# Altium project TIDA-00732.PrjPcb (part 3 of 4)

## Sheet TIDA-00732_Pwr.SchDoc: LDO's Isolated & Non Isolated
size 431 x 279 mm; Date: Not shown in title block; ApprovedBy: Not shown in title block; CheckedBy: Not shown in title block; Author: Not shown in title block; CompanyName: Not shown in title block; DrawnBy: Anbu Mani; Engineer: Not shown in title block; Organization: Not shown in title block; Address1: Not shown in title block; Address2: Not shown in title block; Address3: Not shown in title block; Address4: Not shown in title block; DocumentNumber: 1; Revision: Use project parameter SCH_Rev; SheetNumber: 7; SheetTotal: 10; PageSetup: Record=PageOptions¦CenterHorizontal=True¦CenterVertical=True¦PrintScale=1.00¦XCorrection=1.00¦YCorrection=1.00¦PrintKind=0¦BorderSize=5000000¦LeftOffset=0¦BottomOffset=0¦Orientation=2¦PaperLength=1000¦PaperWidth=1000¦Scale=100¦PaperSource=15¦PrintQuality=600¦MediaType=1¦DitherType=10¦PaperKind=Letter¦PrintScaleMode=1
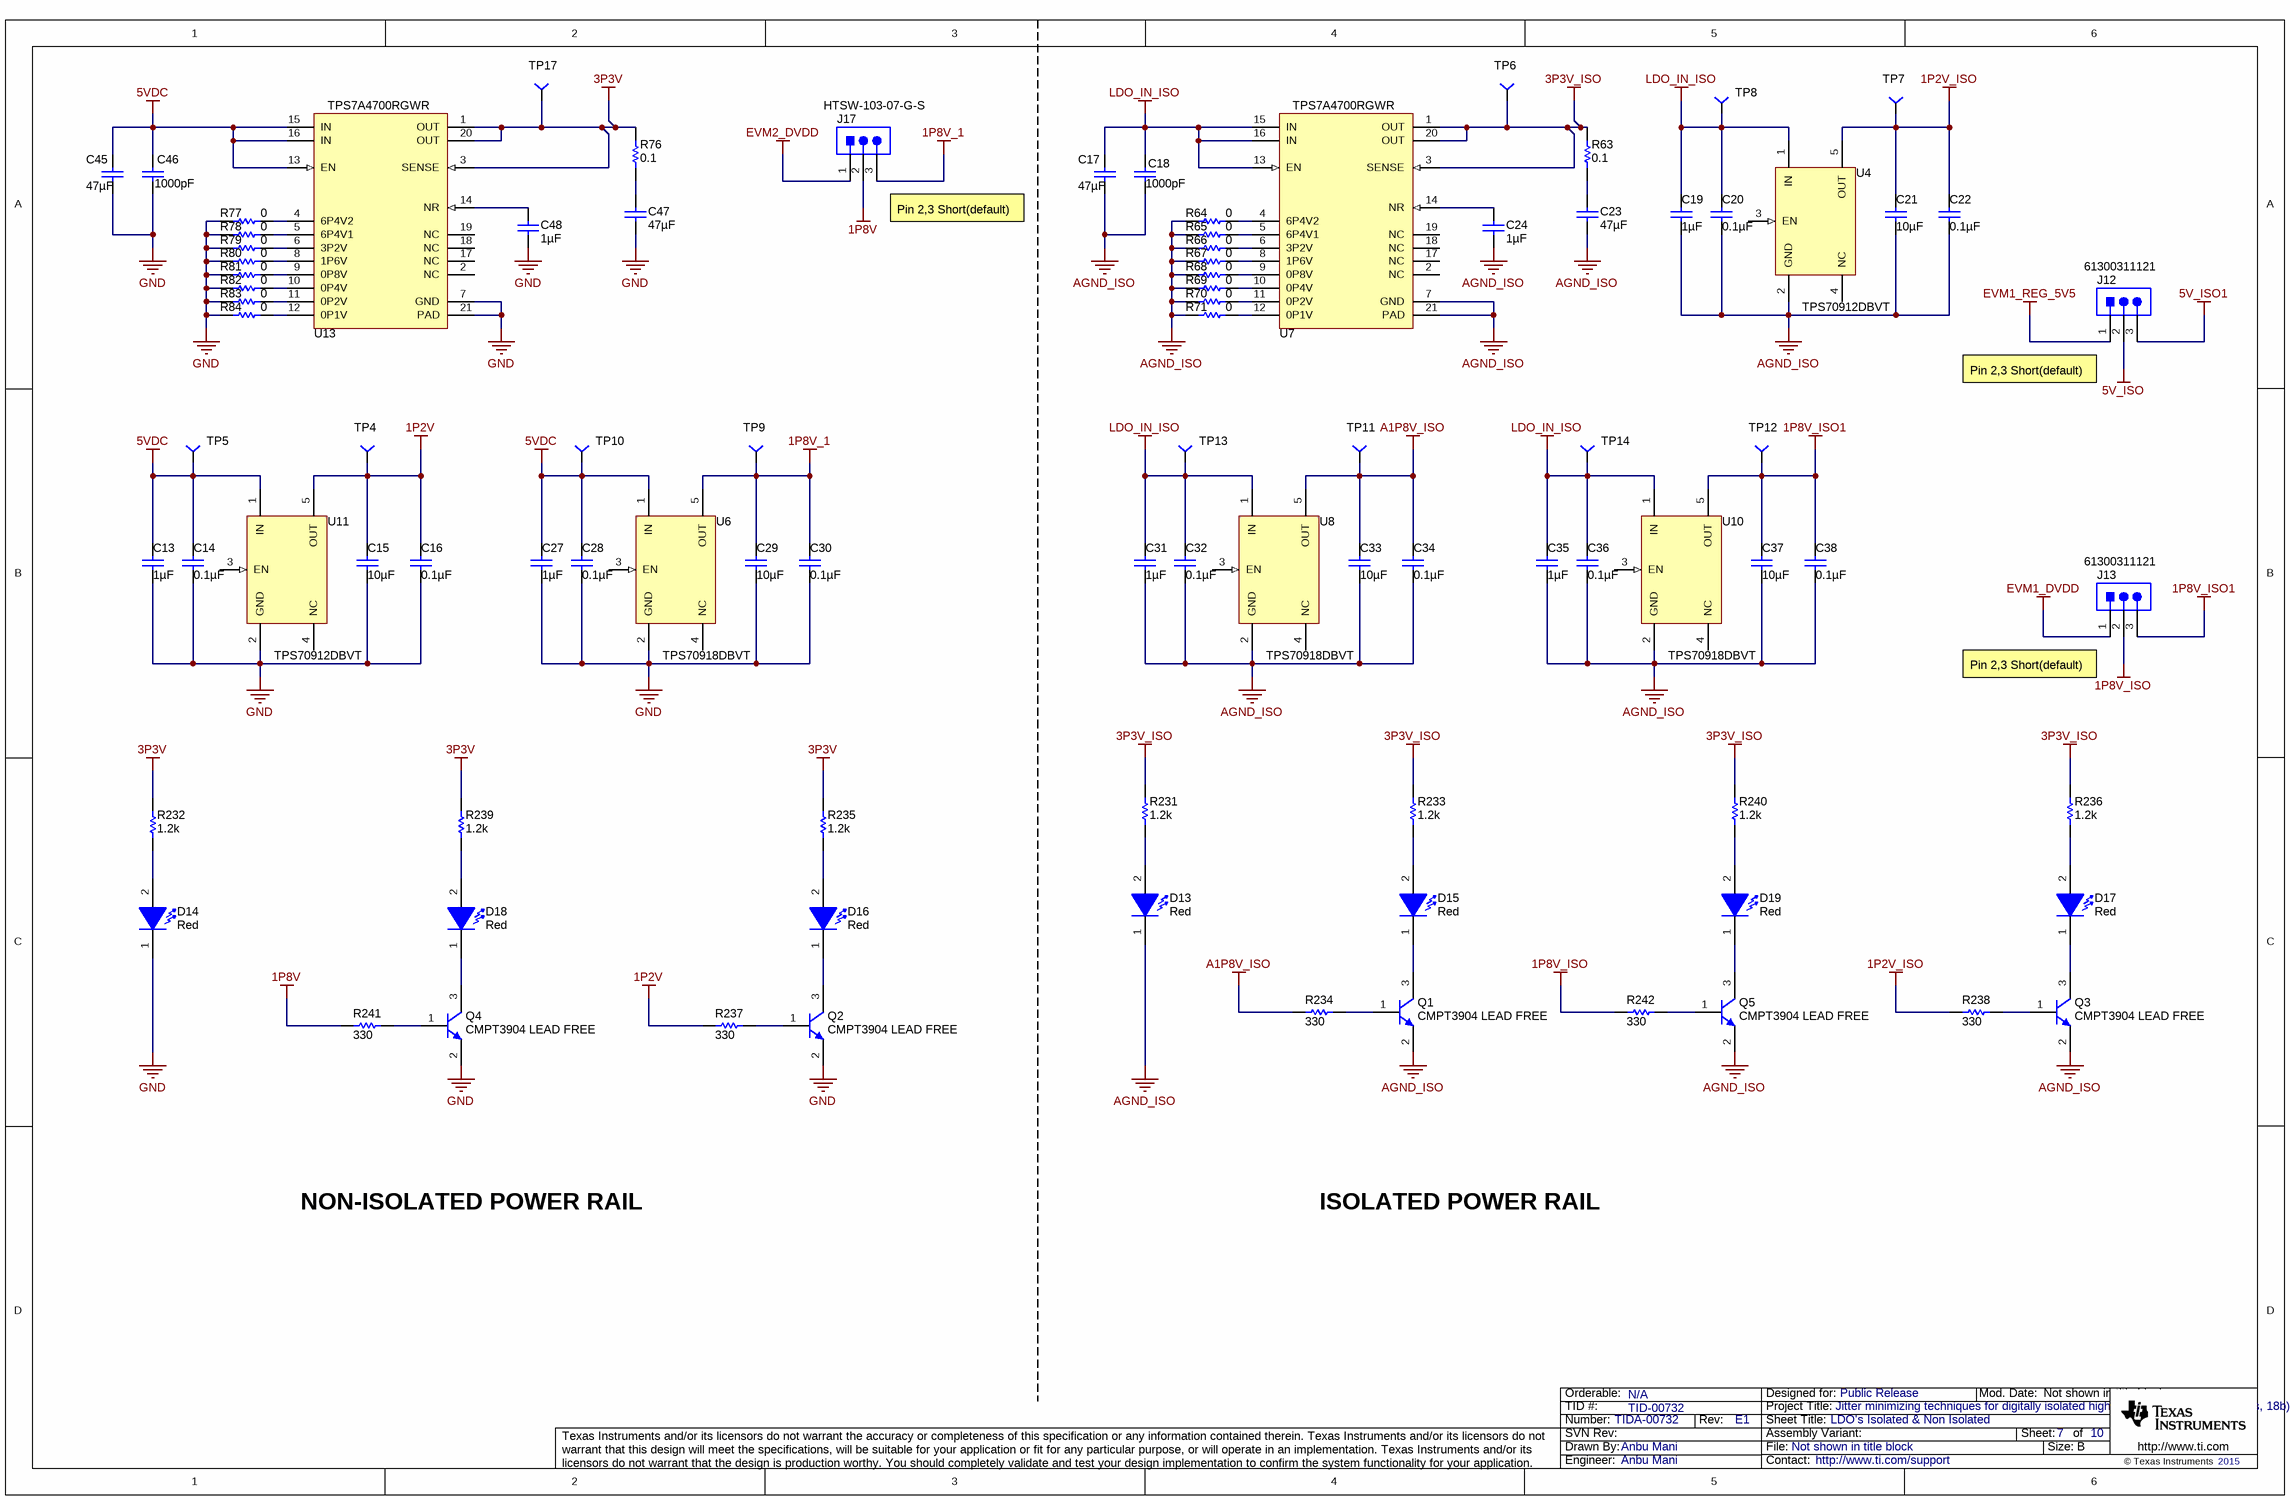
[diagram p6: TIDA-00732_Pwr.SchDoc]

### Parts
C13  ValueDisplayed: 1µF  [0805]  (hidden comment: 08055C105KAT2A)
C14  ValueDisplayed: 0.1µF  [0603]  (hidden comment: C0603C104K5RACTU)
C15  ValueDisplayed: 10µF  [0805]  (hidden comment: 0805YD106MAT2A)
C16  ValueDisplayed: 0.1µF  [0603]  (hidden comment: C0603C104K5RACTU)
C17  ValueDisplayed: 47µF  [1206_190]  (hidden comment: C3216X5R1E476M160AC)
C18  ValueDisplayed: 1000pF  [0603]  (hidden comment: GRM1885C1H102FA01J)
C19  ValueDisplayed: 1µF  [0805]  (hidden comment: 08055C105KAT2A)
C20  ValueDisplayed: 0.1µF  [0603]  (hidden comment: C0603C104K5RACTU)
C21  ValueDisplayed: 10µF  [0805]  (hidden comment: 0805YD106MAT2A)
C22  ValueDisplayed: 0.1µF  [0603]  (hidden comment: C0603C104K5RACTU)
C23  ValueDisplayed: 47µF  [1206_190]  (hidden comment: C3216X5R1E476M160AC)
C24  ValueDisplayed: 1µF  [0603]  (hidden comment: GRM188R71E105KA12D)
C27  ValueDisplayed: 1µF  [0805]  (hidden comment: 08055C105KAT2A)
C28  ValueDisplayed: 0.1µF  [0603]  (hidden comment: C0603C104K5RACTU)
C29  ValueDisplayed: 10µF  [0805]  (hidden comment: 0805YD106MAT2A)
C30  ValueDisplayed: 0.1µF  [0603]  (hidden comment: C0603C104K5RACTU)
C31  ValueDisplayed: 1µF  [0805]  (hidden comment: 08055C105KAT2A)
C32  ValueDisplayed: 0.1µF  [0603]  (hidden comment: C0603C104K5RACTU)
C33  ValueDisplayed: 10µF  [0805]  (hidden comment: 0805YD106MAT2A)
C34  ValueDisplayed: 0.1µF  [0603]  (hidden comment: C0603C104K5RACTU)
C35  ValueDisplayed: 1µF  [0805]  (hidden comment: 08055C105KAT2A)
C36  ValueDisplayed: 0.1µF  [0603]  (hidden comment: C0603C104K5RACTU)
C37  ValueDisplayed: 10µF  [0805]  (hidden comment: 0805YD106MAT2A)
C38  ValueDisplayed: 0.1µF  [0603]  (hidden comment: C0603C104K5RACTU)
C45  ValueDisplayed: 47µF  [1206_190]  (hidden comment: C3216X5R1E476M160AC)
C46  ValueDisplayed: 1000pF  [0603]  (hidden comment: GRM1885C1H102FA01J)
C47  ValueDisplayed: 47µF  [1206_190]  (hidden comment: C3216X5R1E476M160AC)
C48  ValueDisplayed: 1µF  [0603]  (hidden comment: GRM188R71E105KA12D)
D13  value Red  [WL-SMCW_RED]  (hidden comment: 150060RS75000)
D14  value Red  [WL-SMCW_RED]  (hidden comment: 150060RS75000)
D15  value Red  [WL-SMCW_RED]  (hidden comment: 150060RS75000)
D16  value Red  [WL-SMCW_RED]  (hidden comment: 150060RS75000)
D17  value Red  [WL-SMCW_RED]  (hidden comment: 150060RS75000)
D18  value Red  [WL-SMCW_RED]  (hidden comment: 150060RS75000)
D19  value Red  [WL-SMCW_RED]  (hidden comment: 150060RS75000)
J12  61300311121  [WURTH_61300311121]
J13  61300311121  [WURTH_61300311121]
J17  HTSW-103-07-G-S  [Samtec_HTSW-103-07-G-S]
Q1  CMPT3904 LEAD FREE  [SOT-23]
Q2  CMPT3904 LEAD FREE  [SOT-23]
Q3  CMPT3904 LEAD FREE  [SOT-23]
Q4  CMPT3904 LEAD FREE  [SOT-23]
Q5  CMPT3904 LEAD FREE  [SOT-23]
R63  ValueDisplayed: 0.1  [0603]  (hidden comment: ERJ-3RSFR10V)
R64  ValueDisplayed: 0  [0402]  (hidden comment: ERJ-2GE0R00X)
R65  ValueDisplayed: 0  [0402]  (hidden comment: ERJ-2GE0R00X)
R66  ValueDisplayed: 0  [0402]  (hidden comment: ERJ-2GE0R00X)
R67  ValueDisplayed: 0  [0402]  (hidden comment: ERJ-2GE0R00X)
R68  ValueDisplayed: 0  [0402]  (hidden comment: ERJ-2GE0R00X)
R69  ValueDisplayed: 0  [0402]  (hidden comment: ERJ-2GE0R00X)
R70  ValueDisplayed: 0  [0402]  (hidden comment: ERJ-2GE0R00X)
R71  ValueDisplayed: 0  [0402]  (hidden comment: ERJ-2GE0R00X)
R76  ValueDisplayed: 0.1  [0603]  (hidden comment: ERJ-3RSFR10V)
R77  ValueDisplayed: 0  [0402]  (hidden comment: ERJ-2GE0R00X)
R78  ValueDisplayed: 0  [0402]  (hidden comment: ERJ-2GE0R00X)
R79  ValueDisplayed: 0  [0402]  (hidden comment: ERJ-2GE0R00X)
R80  ValueDisplayed: 0  [0402]  (hidden comment: ERJ-2GE0R00X)
R81  ValueDisplayed: 0  [0402]  (hidden comment: ERJ-2GE0R00X)
R82  ValueDisplayed: 0  [0402]  (hidden comment: ERJ-2GE0R00X)
R83  ValueDisplayed: 0  [0402]  (hidden comment: ERJ-2GE0R00X)
R84  ValueDisplayed: 0  [0402]  (hidden comment: ERJ-2GE0R00X)
R231  ValueDisplayed: 1.2k  [0603]  (hidden comment: CRCW06031K20JNEA)
R232  ValueDisplayed: 1.2k  [0603]  (hidden comment: CRCW06031K20JNEA)
R233  ValueDisplayed: 1.2k  [0603]  (hidden comment: CRCW06031K20JNEA)
R234  ValueDisplayed: 330  [0603]  (hidden comment: RC0603JR-07330RL)
R235  ValueDisplayed: 1.2k  [0603]  (hidden comment: CRCW06031K20JNEA)
R236  ValueDisplayed: 1.2k  [0603]  (hidden comment: CRCW06031K20JNEA)
R237  ValueDisplayed: 330  [0603]  (hidden comment: RC0603JR-07330RL)
R238  ValueDisplayed: 330  [0603]  (hidden comment: RC0603JR-07330RL)
R239  ValueDisplayed: 1.2k  [0603]  (hidden comment: CRCW06031K20JNEA)
R240  ValueDisplayed: 1.2k  [0603]  (hidden comment: CRCW06031K20JNEA)
R241  ValueDisplayed: 330  [0603]  (hidden comment: RC0603JR-07330RL)
R242  ValueDisplayed: 330  [0603]  (hidden comment: RC0603JR-07330RL)
TP4  TP1_PD40_D0.5_S50  [TP-040_RND]  (value not drawn)
TP5  TP1_PD40_D0.5_S50  [TP-040_RND]  (value not drawn)
TP6  TP1_PD40_D0.5_S50  [TP-040_RND]  (value not drawn)
TP7  TP1_PD40_D0.5_S50  [TP-040_RND]  (value not drawn)
TP8  TP1_PD40_D0.5_S50  [TP-040_RND]  (value not drawn)
TP9  TP1_PD40_D0.5_S50  [TP-040_RND]  (value not drawn)
TP10  TP1_PD40_D0.5_S50  [TP-040_RND]  (value not drawn)
TP11  TP1_PD40_D0.5_S50  [TP-040_RND]  (value not drawn)
TP12  TP1_PD40_D0.5_S50  [TP-040_RND]  (value not drawn)
TP13  TP1_PD40_D0.5_S50  [TP-040_RND]  (value not drawn)
TP14  TP1_PD40_D0.5_S50  [TP-040_RND]  (value not drawn)
TP17  TP1_PD40_D0.5_S50  [TP-040_RND]  (value not drawn)
U4  TPS70912DBVT  [DBV0005A_N]
U6  TPS70918DBVT  [DBV0005A_N]
U7  TPS7A4700RGWR  [RGW0020A]
U8  TPS70918DBVT  [DBV0005A_N]
U10  TPS70918DBVT  [DBV0005A_N]
U11  TPS70912DBVT  [DBV0005A_N]
U13  TPS7A4700RGWR  [RGW0020A]

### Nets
1P2V: C15.1 C16.1 R237.2 TP4.1 U11.5(OUT)
1P2V_ISO: C21.1 C22.1 R238.2 TP7.1 U4.5(OUT)
1P8V: J17.2 R241.2
1P8V_1: C29.1 C30.1 J17.3 TP9.1 U6.5(OUT)
1P8V_ISO: J13.2 R242.2
1P8V_ISO1: C37.1 C38.1 J13.3 TP12.1 U10.5(OUT)
3P3V: R76.2 R232.2 R235.2 R239.2 TP17.1 U13.1(OUT) U13.3(SENSE) U13.20(OUT)
3P3V_ISO: R63.2 R231.2 R233.2 R236.2 R240.2 TP6.1 U7.1(OUT) U7.3(SENSE) U7.20(OUT)
5V_ISO: J12.2
5V_ISO1: J12.3
5VDC: C13.1 C14.1 C27.1 C28.1 C45.1 C46.1 TP5.1 TP10.1 U6.1(IN) U11.1(IN) U13.13(EN) U13.15(IN) U13.16(IN)
A1P8V_ISO: C33.1 C34.1 R234.2 TP11.1 U8.5(OUT)
AGND_ISO: C17.2 C18.2 C19.2 C20.2 C21.2 C22.2 C23.2 C24.1 C31.2 C32.2 C33.2 C34.2 C35.2 C36.2 C37.2 C38.2 D13.1(K) Q1.2(E) Q3.2(E) Q5.2(E) R64.1 R65.1 R66.1 R67.1 R68.1 R69.1 R70.1 R71.1 U4.2(GND) U7.7(GND) U7.21(PAD) U8.2(GND) U10.2(GND)
EVM1_DVDD: J13.1
EVM1_REG_5V5: J12.1
EVM2_DVDD: J17.1
GND: C13.2 C14.2 C15.2 C16.2 C27.2 C28.2 C29.2 C30.2 C45.2 C46.2 C47.2 C48.1 D14.1(K) Q2.2(E) Q4.2(E) R77.1 R78.1 R79.1 R80.1 R81.1 R82.1 R83.1 R84.1 U6.2(GND) U11.2(GND) U13.7(GND) U13.21(PAD)
LDO_IN_ISO: C17.1 C18.1 C19.1 C20.1 C31.1 C32.1 C35.1 C36.1 TP8.1 TP13.1 TP14.1 U4.1(IN) U7.13(EN) U7.15(IN) U7.16(IN) U8.1(IN) U10.1(IN)
NetC23_1: C23.1 R63.1
NetC24_2: C24.2 U7.14(NR)
NetC47_1: C47.1 R76.1
NetC48_2: C48.2 U13.14(NR)
NetD13_2: D13.2(A) R231.1
NetD14_2: D14.2(A) R232.1
NetD15_1: D15.1(K) Q1.3(C)
NetD15_2: D15.2(A) R233.1
NetD16_1: D16.1(K) Q2.3(C)
NetD16_2: D16.2(A) R235.1
NetD17_1: D17.1(K) Q3.3(C)
NetD17_2: D17.2(A) R236.1
NetD18_1: D18.1(K) Q4.3(C)
NetD18_2: D18.2(A) R239.1
NetD19_1: D19.1(K) Q5.3(C)
NetD19_2: D19.2(A) R240.1
NetQ1_1: Q1.1(B) R234.1
NetQ2_1: Q2.1(B) R237.1
NetQ3_1: Q3.1(B) R238.1
NetQ4_1: Q4.1(B) R241.1
NetQ5_1: Q5.1(B) R242.1
NetR64_2: R64.2 U7.4(6P4V2)
NetR65_2: R65.2 U7.5(6P4V1)
NetR66_2: R66.2 U7.6(3P2V)
NetR67_2: R67.2 U7.8(1P6V)
NetR68_2: R68.2 U7.9(0P8V)
NetR69_2: R69.2 U7.10(0P4V)
NetR70_2: R70.2 U7.11(0P2V)
NetR71_2: R71.2 U7.12(0P1V)
NetR77_2: R77.2 U13.4(6P4V2)
NetR78_2: R78.2 U13.5(6P4V1)
NetR79_2: R79.2 U13.6(3P2V)
NetR80_2: R80.2 U13.8(1P6V)
NetR81_2: R81.2 U13.9(0P8V)
NetR82_2: R82.2 U13.10(0P4V)
NetR83_2: R83.2 U13.11(0P2V)
NetR84_2: R84.2 U13.12(0P1V)

Not connected (* = marked no-connect by the designer): U4 3(EN) 4(NC); U6 3(EN) 4(NC); U7 2(NC) 17(NC) 18(NC) 19(NC); U8 3(EN) 4(NC); U10 3(EN) 4(NC); U11 3(EN) 4(NC); U13 2(NC) 17(NC) 18(NC) 19(NC)

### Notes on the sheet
- (near J17) Pin 2,3 Short(default)
- (near J12) Pin 2,3 Short(default)
- (near J13) Pin 2,3 Short(default)
- NON-ISOLATED POWER RAIL
- ISOLATED POWER RAIL

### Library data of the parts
C13 C19 C27 C31 C35 = 08055C105KAT2A: CAP, CERM, 1uF, 50V, +/-10%, X7R, 0805; Manufacturer: AVX; Polarized: N; CompType: Capacitor; U/M: EA; Cap_F: 0.000001; Tolerance_%: 10; Value1: Unknown; VDC_V: 50; TaMin_C: -55; TaMax_C: 125
C14 C16 C20 C22 C28 C30 C32 C34 C36 C38 = C0603C104K5RACTU: CAP, CERM, 0.1uF, 50V, +/-10%, X7R, 0603; Manufacturer: Kemet; Polarized: N; CompType: Capacitor; U/M: EA; Cap_F: 0.0000001; Tolerance_%: 10; Value1: Unknown; VDC_V: 50; TaMin_C: -55; TaMax_C: 125
C15 C21 C29 C33 C37 = 0805YD106MAT2A: CAP, CERM, 10uF, 16V, +/-20%, X5R, 0805; Manufacturer: AVX; Polarized: N; CompType: Capacitor; U/M: EA; Cap_F: 0.00001; Tolerance_%: 20; Value1: Unknown; VDC_V: 16; TaMin_C: -55; TaMax_C: 85
C17 C23 C45 C47 = C3216X5R1E476M160AC: CAP, CERM, 47 µF, 25 V, +/- 20%, X5R, 1206_190; Manufacturer: TDK; Polarized: N; CompType: Capacitor; Value: 47uF; U/M: EA; Cap_F: 0.000047; Tolerance_%: 20; Value1: Unknown; VDC_V: 25; Value2: 25V; TaMin_C: -55; TaMax_C: 85; Cap_Case: 1206; AEC Category: Q200
C18 C46 = GRM1885C1H102FA01J: CAP, CERM, 1000 pF, 50 V, +/- 1%, C0G/NP0, 0603; Manufacturer: MuRata; Polarized: N; CompType: Capacitor; Value: 1000pF; U/M: EA; Cap_F: 0.000000001; Tolerance_%: 1; Value1: Unknown; VDC_V: 50; Value2: 50V; TaMin_C: -55; TaMax_C: 125; AEC Category: Q200
C24 C48 = GRM188R71E105KA12D: CAP, CERM, 1 µF, 25 V, +/- 10%, X7R, 0603; Manufacturer: MuRata; Polarized: N; CompType: Capacitor; Value: 1uF; U/M: EA; Cap_F: 0.000001; Tolerance_%: 10; Value1: Unknown; VDC_V: 25; Value2: 25V; TaMin_C: -55; TaMax_C: 125; AEC Category: Q200
D13-D19 = 150060RS75000: LED, Red, SMD; Manufacturer: Wurth Elektronik; Type: AlInGaP; Vf_V: 2; Value2: 2V; Io_A: 0.03; Vr_V: 5; Tjmax_C: 85; Power_TotalModule: 0.072; Value1: 0.072W; Angle: 140; U/M: EA
J12 J13 = 61300311121: Header, 2.54 mm, 3x1, Gold, TH; Manufacturer: Wurth Elektronik eiSos; SymbolCreator: a0799628; U/M: EA
J17 = HTSW-103-07-G-S: Header, 100mil, 3x1, Gold, TH; Manufacturer: Samtec; SymbolCreator: a0799628; U/M: EA
Q1-Q5 = CMPT3904 LEAD FREE, Central Semiconductor: Transistor, NPN, 40 V, 0.2 A, SOT-23; CompType: BJT; PNP: 0; NPN: 1; Vceo_V: 40; Vcesat1_V: 0.2; Value: 40 V; Value1: 0.2 A; TaMin_C: -65; TaMax_C: 150; U/M: EA; AEC Category: Q101
R63 R76 = ERJ-3RSFR10V: RES, 0.1, 1%, 0.1 W, 0603; Manufacturer: Panasonic; CompType: Resistor; Value: 0.1; Value_Code: R100; Tolerance_%: 1; Value2: 0.1W; TempCo: 300 ppm/C; EIA_Code: E96; U/M: EA; AEC Category: Q200
R64-R71 R77-R84 = ERJ-2GE0R00X: RES, 0, 5%, 0.063 W, 0402; Manufacturer: Panasonic; CompType: Resistor; Value: 0; Value_Code: 0000; Tolerance_%: 5; Power_W: 0.063; Value2: 0.063W; VDC_V: 50; TempCo: 600 ppm/C; EIA_Code: E24; U/M: EA; AEC Category: Q200
R231-R233 R235 R236 R239 R240 = CRCW06031K20JNEA: RES, 1.2 k, 5%, 0.1 W, 0603; Manufacturer: Vishay-Dale; CompType: Resistor; Value: 1.2k; Res_ohm: 1200; Value_Code: 1k20; Tolerance_%: 5; Power_W: 0.1; Value2: 0.1W; VDC_V: 75; TempCo: 200 ppm/C; EIA_Code: E24; U/M: EA; AEC Category: Q200
R234 R237 R238 R241 R242 = RC0603JR-07330RL: RES, 330, 5%, 0.1 W, 0603; Manufacturer: Yageo America; CompType: Resistor; Value: 330; Value_Code: 330R; Tolerance_%: 5; Power_W: 0.1; Value2: 0.1W; VDC_V: 50; TempCo: 100 ppm/C; EIA_Code: E24; U/M: EA; AEC Category: Q200
TP4-TP14 TP17 = TP-040_RND: Test Point 40mil pad 20mil drill; Manufacturer: STD; Value: STD
U4 U11 = TPS70933DBVT: IC REG LDO 1.2V 0.15A SOT23-5; Alternate Manufacturer: None; Manufacturer: Texas Instruments; SymbolCreator: a0411947; U/M: EA
U6 U8 U10 = TPS70933DBVT: IC REG LDO 1.8V 0.15A SOT23-5; Alternate Manufacturer: None; Manufacturer: Texas Instruments; SymbolCreator: a0411947; U/M: EA
U7 U13 = TPS7A4700RGWR: 36-V, 1-A, 4.17-μVRMS, RF LDO Voltage Regulator, RGW0020A; Alternate PartNumber: TPS7A4700RGWT; Manufacturer: Texas Instruments; SymbolCreator: a0412235; CompType: IC; U/M: EA

## Sheet TIDA-00732_Pwr_Sense.SchDoc: Power Sense - PH1 & PH2  Interface
size 431 x 279 mm; Date: Not shown in title block; ApprovedBy: Not shown in title block; CheckedBy: Not shown in title block; Author: Not shown in title block; CompanyName: Not shown in title block; DrawnBy: Anbu Mani; Engineer: Not shown in title block; Organization: Not shown in title block; Address1: Not shown in title block; Address2: Not shown in title block; Address3: Not shown in title block; Address4: Not shown in title block; DocumentNumber: 1; Revision: Use project parameter SCH_Rev; SheetNumber: 8; SheetTotal: 10; PageSetup: Record=PageOptions¦CenterHorizontal=True¦CenterVertical=True¦PrintScale=1.00¦XCorrection=1.00¦YCorrection=1.00¦PrintKind=0¦BorderSize=5000000¦LeftOffset=0¦BottomOffset=0¦Orientation=2¦PaperLength=1000¦PaperWidth=1000¦Scale=100¦PaperSource=15¦PrintQuality=600¦MediaType=1¦DitherType=10¦PaperKind=Letter¦PrintScaleMode=1
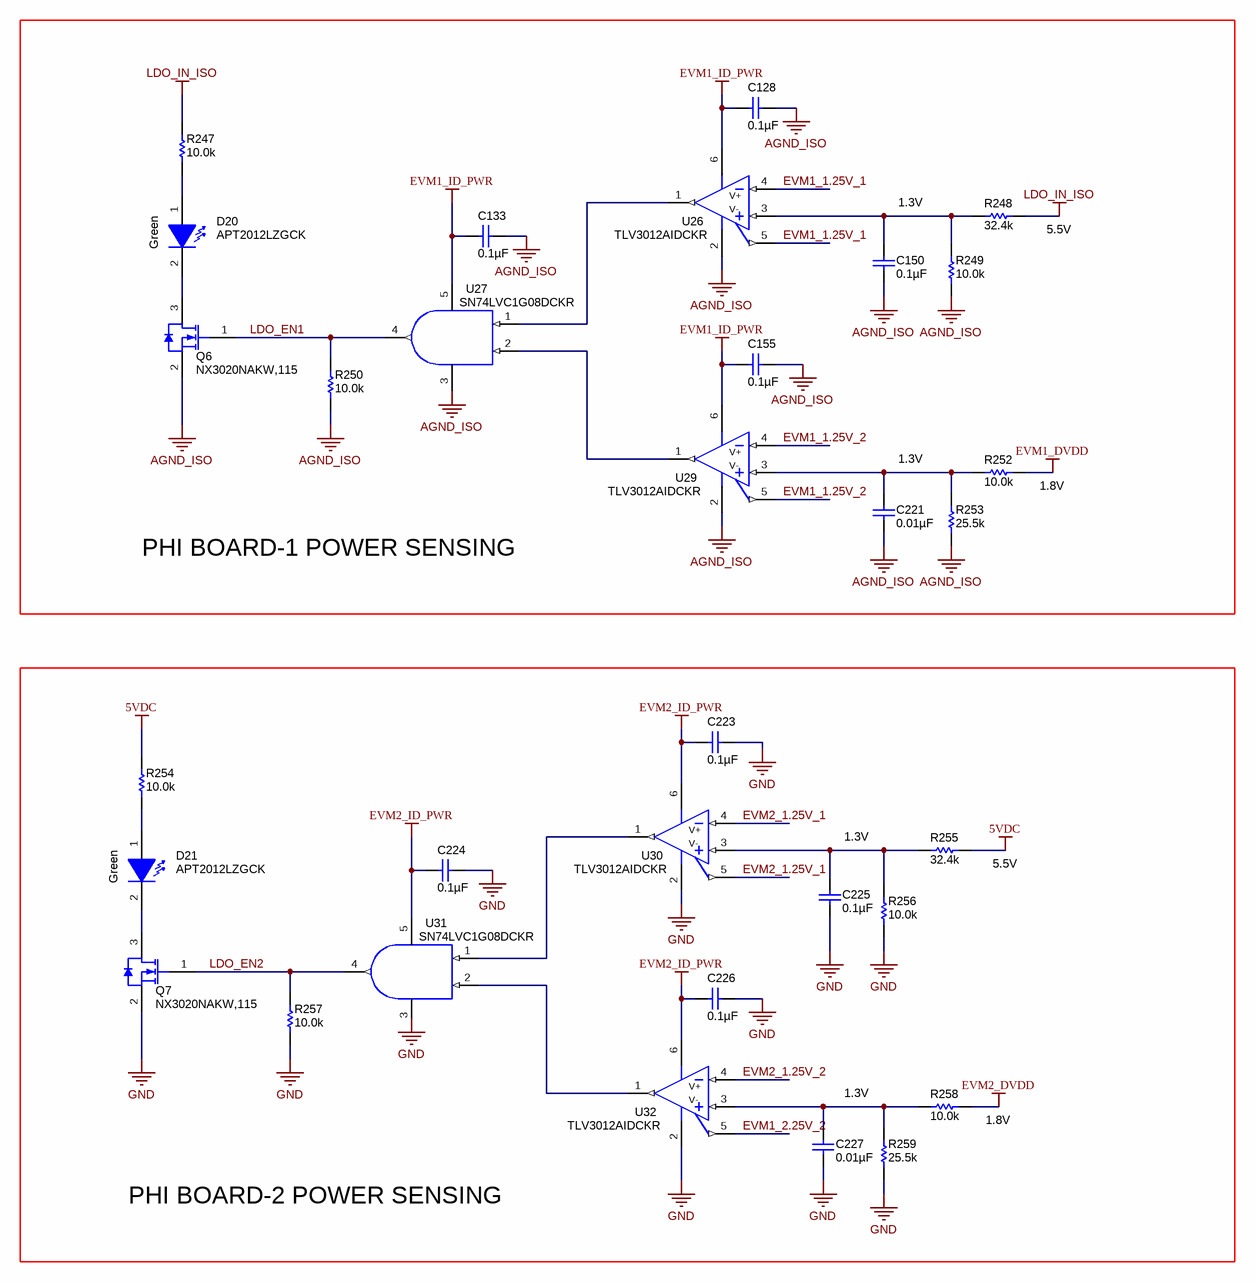
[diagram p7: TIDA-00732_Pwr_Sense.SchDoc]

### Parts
C128  ValueDisplayed: 0.1µF  [0402]  (hidden comment: GRM155R71C104KA88D)
C133  ValueDisplayed: 0.1µF  [0402]  (hidden comment: GRM155R71C104KA88D)
C150  ValueDisplayed: 0.1µF  [0402]  (hidden comment: GRM155R71C104KA88D)
C155  ValueDisplayed: 0.1µF  [0402]  (hidden comment: GRM155R71C104KA88D)
C221  ValueDisplayed: 0.01µF  [0402]  (hidden comment: GRM155R71H103KA88D)
C223  ValueDisplayed: 0.1µF  [0402]  (hidden comment: GRM155R71C104KA88D)
C224  ValueDisplayed: 0.1µF  [0402]  (hidden comment: GRM155R71C104KA88D)
C225  ValueDisplayed: 0.1µF  [0402]  (hidden comment: GRM155R71C104KA88D)
C226  ValueDisplayed: 0.1µF  [0402]  (hidden comment: GRM155R71C104KA88D)
C227  ValueDisplayed: 0.01µF  [0402]  (hidden comment: GRM155R71H103KA88D)
D20  value Green  [APT2012_Green]  (hidden comment: APT2012LZGCK)
D21  value Green  [APT2012_Green]  (hidden comment: APT2012LZGCK)
Q6  NX3020NAKW,115  [SOT-323]
Q7  NX3020NAKW,115  [SOT-323]
R247  ValueDisplayed: 10.0k  [0402]  (hidden comment: ERJ-2RKF1002X)
R248  ValueDisplayed: 32.4k  [0603_HV]  (hidden comment: RG1608P-3242-B-T5)
R249  ValueDisplayed: 10.0k  [0603_HV]  (hidden comment: RG1608P-103-B-T5)
R250  ValueDisplayed: 10.0k  [0402]  (hidden comment: ERJ-2RKF1002X)
R252  ValueDisplayed: 10.0k  [0603_HV]  (hidden comment: RG1608P-103-B-T5)
R253  ValueDisplayed: 25.5k  [0603_HV]  (hidden comment: RG1608P-2552-B-T5)
R254  ValueDisplayed: 10.0k  [0402]  (hidden comment: ERJ-2RKF1002X)
R255  ValueDisplayed: 32.4k  [0603_HV]  (hidden comment: RG1608P-3242-B-T5)
R256  ValueDisplayed: 10.0k  [0603_HV]  (hidden comment: RG1608P-103-B-T5)
R257  ValueDisplayed: 10.0k  [0402]  (hidden comment: ERJ-2RKF1002X)
R258  ValueDisplayed: 10.0k  [0603_HV]  (hidden comment: RG1608P-103-B-T5)
R259  ValueDisplayed: 25.5k  [0603_HV]  (hidden comment: RG1608P-2552-B-T5)
U26  TLV3012AIDCKR  [DCK0006A_L]
U27  SN74LVC1G08DCKR  [DCK0005A_L]
U29  TLV3012AIDCKR  [DCK0006A_L]
U30  TLV3012AIDCKR  [DCK0006A_L]
U31  SN74LVC1G08DCKR  [DCK0005A_L]
U32  TLV3012AIDCKR  [DCK0006A_L]

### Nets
5VDC: R254.2 R255.2
AGND_ISO: C128.1 C133.1 C150.2 C155.1 C221.2 Q6.2(S) R249.1 R250.1 R253.1 U26.2(V-) U27.3(V-) U29.2(V-)
EVM1_DVDD: R252.2
EVM1_ID_PWR: C128.2 C133.2 C155.2 U26.6(V+) U27.5(V+) U29.6(V+)
EVM2_DVDD: R258.2
EVM2_ID_PWR: C223.2 C224.2 C226.2 U30.6(V+) U31.5(V+) U32.6(V+)
GND: C223.1 C224.1 C225.2 C226.1 C227.2 Q7.2(S) R256.1 R257.1 R259.1 U30.2(V-) U32.2(V-)
LDO_IN_ISO: R247.2 R248.2
EVM1_1.25V_1: U26.4(IN-) U26.5(REF)
EVM1_1.25V_2: U29.4(IN-) U29.5(REF)
EVM1_2.25V_2: U32.5(REF)
EVM2_1.25V_1: U30.4(IN-) U30.5(REF)
EVM2_1.25V_2: U32.4(IN-)
LDO_EN1: Q6.1(G) R250.2 U27.4(Y)
LDO_EN2: Q7.1(G) R257.2 U31.4(Y)
NetC150_1: C150.1 R248.1 R249.2 U26.3(IN+)
NetC221_1: C221.1 R252.1 R253.2 U29.3(IN+)
NetC225_1: C225.1 R255.1 R256.2 U30.3(IN+)
NetC227_1: C227.1 R258.1 R259.2 U32.3(IN+)
NetD20_1: D20.1(A) R247.1
NetD20_2: D20.2(K) Q6.3(D)
NetD21_1: D21.1(A) R254.1
NetD21_2: D21.2(K) Q7.3(D)
NetU26_1: U26.1(OUT) U27.1(A)
NetU27_2: U27.2(B) U29.1(OUT)
NetU30_1: U30.1(OUT) U31.1(A)
NetU31_2: U31.2(B) U32.1(OUT)

Not connected (* = marked no-connect by the designer): U31 3(V-)

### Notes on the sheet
- 1.3V
- (near R248) 5.5V
- (near R252) 1.8V
- PHI BOARD-1 POWER SENSING
- (near R255) 5.5V
- (near R258) 1.8V
- PHI BOARD-2 POWER SENSING
- Labels drawn without touching a wire or pin: GND

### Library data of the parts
C128 C133 C150 C155 C223-C226 = GRM155R71C104KA88D: CAP, CERM, 0.1 µF, 16 V, +/- 10%, X7R, 0402; Manufacturer: MuRata; Polarized: N; CompType: Capacitor; Value: 0.1uF; U/M: EA; Cap_F: 0.0000001; Tolerance_%: 10; Value1: Unknown; VDC_V: 16; Value2: 16V; TaMin_C: -55; TaMax_C: 125; AEC Category: Q200
C221 C227 = GRM155R71H103KA88D: CAP, CERM, 0.01 µF, 50 V, +/- 10%, X7R, 0402; Manufacturer: MuRata; Polarized: N; CompType: Capacitor; Value: 0.01uF; U/M: EA; Cap_F: 0.00000001; Tolerance_%: 10; Value1: Unknown; VDC_V: 50; Value2: 50V; TaMin_C: -55; TaMax_C: 125; AEC Category: Q200
D20 D21 = APT2012LZGCK: LED, Green, SMD; Manufacturer: Kingbright; Type: InGaN; Vf_V: 2.65; Value2: 2.65V; Io_A: 0.002; Vr_V: 5; Ir_A: 5e-005; Tjmax_C: 85; Power_TotalModule: 0.075; Value1: 0.075W; Angle: 120; U/M: EA
Q6 Q7 = NX3020NAKW,115: MOSFET, N-CH, 30 V, 0.18 A, SOT-323; Manufacturer: NXP Semiconductor; Alternate Manufacturer: None; U/M: EA; ChType: N; Value: 30V; VdsMax_V: 30; Value1: 5.2 ohm; Rdson45_ohm: 5.2; Value2: 0.34 nC; QgTyp_nC: 0.34; Vgs_V: 20; IdsMax_A: 0.18; AEC Category: Q101
R247 R250 R254 R257 = ERJ-2RKF1002X: RES, 10.0 k, 1%, 0.1 W, 0402; Manufacturer: Panasonic; CompType: Resistor; Value: 10.0k; Res_ohm: 10000; Value_Code: 10k0; Tolerance_%: 1; Power_W: 0.1; Value2: 0.1W; VDC_V: 50; TempCo: 100 ppm/C; EIA_Code: E96; U/M: EA; AEC Category: Q200
R248 R255 = RG1608P-3242-B-T5: RES, 32.4 k, 0.1%, 0.1 W, 0603; Manufacturer: Susumu Co Ltd; CompType: Resistor; Value: 32.4k; Res_ohm: 32400; Value_Code: 32k4; Tolerance_%: 0.1; Value2: 0.1W; VDC_V: 75; TempCo: 25 ppm/C; EIA_Code: E192; U/M: EA; AEC Category: Q200
R249 R252 R256 R258 = RG1608P-103-B-T5: RES, 10.0 k, 0.1%, 0.1 W, 0603; Manufacturer: Susumu Co Ltd; CompType: Resistor; Value: 10.0k; Res_ohm: 10000; Value_Code: 10k0; Tolerance_%: 0.1; Value2: 0.1W; VDC_V: 75; TempCo: 25 ppm/C; EIA_Code: E192; U/M: EA; AEC Category: Q200
R253 R259 = RG1608P-2552-B-T5: RES, 25.5 k, 0.1%, 0.1 W, 0603; Manufacturer: Susumu Co Ltd; CompType: Resistor; Value: 25.5k; Res_ohm: 25500; Value_Code: 25k5; Tolerance_%: 0.1; Value2: 0.1W; VDC_V: 75; TempCo: 25 ppm/C; EIA_Code: E192; U/M: EA; AEC Category: Q200
U26 U29 U30 U32 = TLV3012AIDCKR: Nanopower, 1.8V, Comparator with Voltage Reference, DCK0006A; Alternate PartNumber: TLV3012AIDCKT; Manufacturer: Texas Instruments; SymbolCreator: a0411595/a0412235; CompType: IC; U/M: EA
U27 U31 = SN74LVC1G08DCKR: Single 2-Input Positive-AND Gate, DCK0005A; Alternate PartNumber: SN74LVC1G08DCKT; Manufacturer: Texas Instruments; CompType: IC; U/M: EA

## Sheet TIDA-00732_ADC_Ref_Select.SchDoc: ADC Reference Selection
size 431 x 279 mm; Date: Not shown in title block; ApprovedBy: Not shown in title block; CheckedBy: Not shown in title block; Author: Not shown in title block; CompanyName: Not shown in title block; DrawnBy: Anbu Mani; Engineer: Not shown in title block; Organization: Not shown in title block; Address1: Not shown in title block; Address2: Not shown in title block; Address3: Not shown in title block; Address4: Not shown in title block; DocumentNumber: 1; Revision: Use project parameter SCH_Rev; SheetNumber: 9; SheetTotal: 10; PageSetup: Record=PageOptions¦CenterHorizontal=True¦CenterVertical=True¦PrintScale=1.00¦XCorrection=1.00¦YCorrection=1.00¦PrintKind=0¦BorderSize=5000000¦LeftOffset=0¦BottomOffset=0¦Orientation=2¦PaperLength=1000¦PaperWidth=1000¦Scale=100¦PaperSource=15¦PrintQuality=600¦MediaType=1¦DitherType=10¦PaperKind=Letter¦PrintScaleMode=1
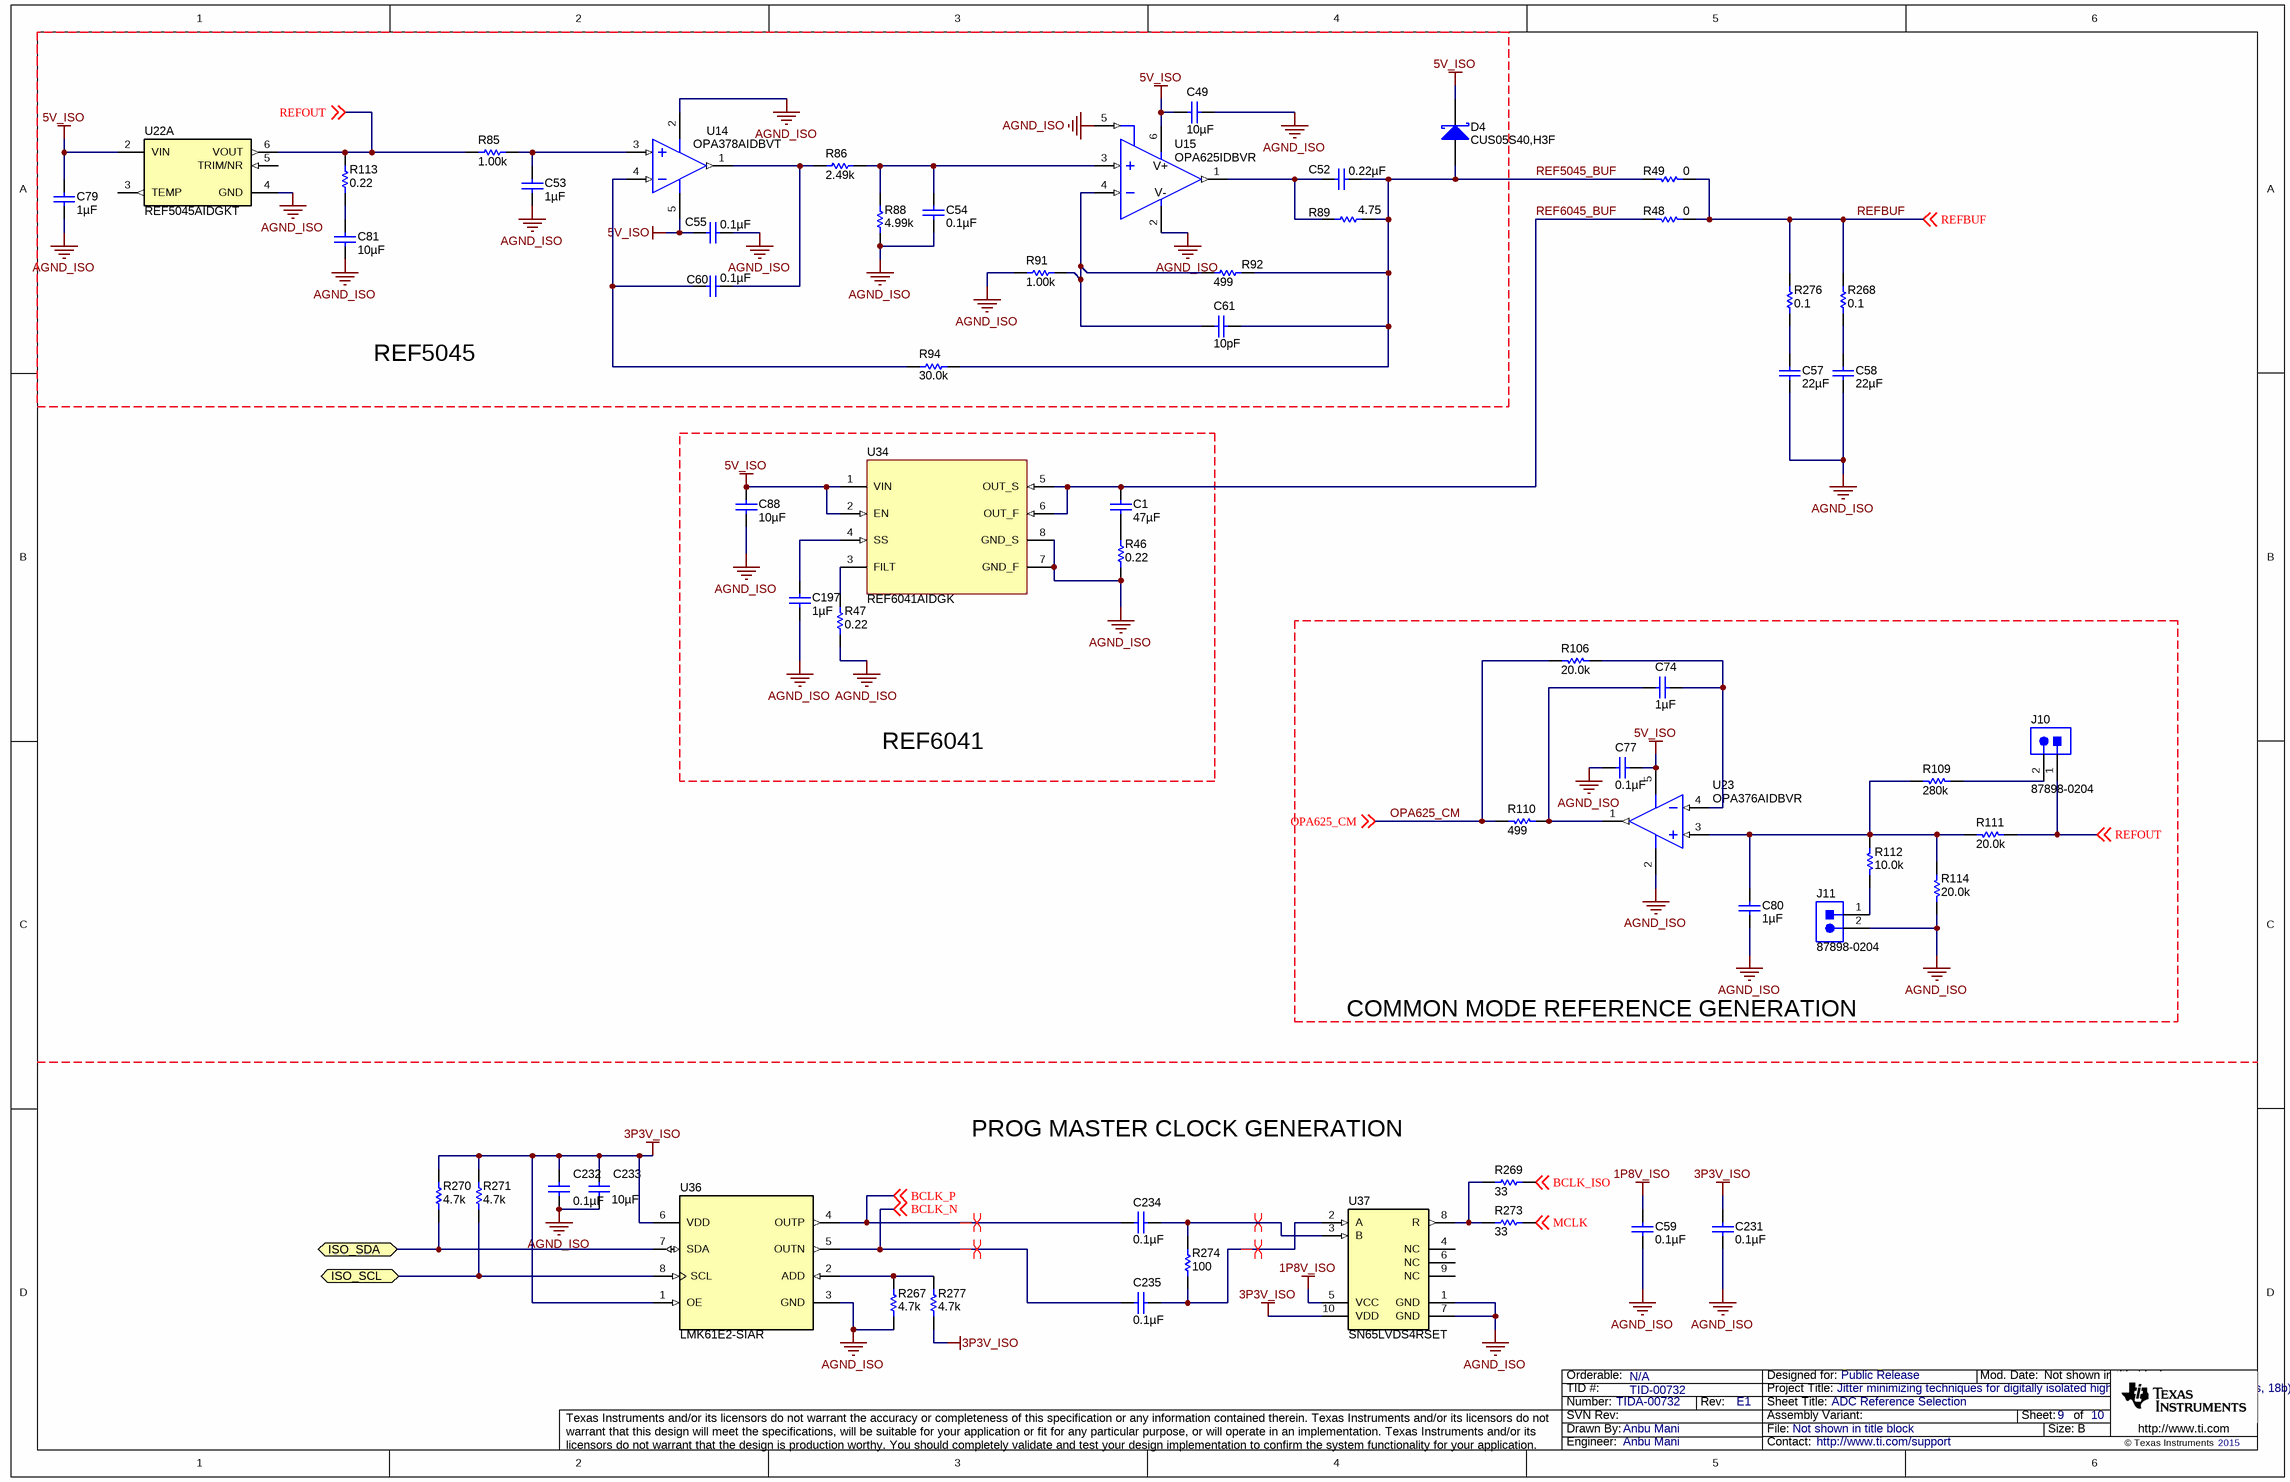
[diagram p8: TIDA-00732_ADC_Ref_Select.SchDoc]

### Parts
C1  ValueDisplayed: 47µF  [1210]  (hidden comment: GRM32ER71A476KE15L)
C49  ValueDisplayed: 10µF  [0603_120]  (hidden comment: ZRB18AD71A106KE01L)
C52  ValueDisplayed: 0.22µF  [0805_HV]  (hidden comment: 0805YC224JAT2A)
C53  ValueDisplayed: 1µF  [0603]  (hidden comment: GRM188R71E105KA12D)
C54  ValueDisplayed: 0.1µF  [0603]  (hidden comment: C0603C104J3RACTU)
C55  ValueDisplayed: 0.1µF  [0603]  (hidden comment: C0603C104J3RACTU)
C57  ValueDisplayed: 22µF  [0603]  (hidden comment: GRM188R60J226MEA0J)
C58  ValueDisplayed: 22µF  [0603]  (hidden comment: GRM188R60J226MEA0J)
C59  ValueDisplayed: 0.1µF  [0402]  (hidden comment: GRM155R71C104KA88D)
C60  ValueDisplayed: 0.1µF  [0603]  (hidden comment: C0603C104J3RACTU)
C61  ValueDisplayed: 10pF  [0603]  (hidden comment: C0603C100F5GAC7867)
C74  ValueDisplayed: 1µF  [0603]  (hidden comment: GRM188R71E105KA12D)
C77  ValueDisplayed: 0.1µF  [0603]  (hidden comment: C0603C104J3RACTU)
C79  ValueDisplayed: 1µF  [0603]  (hidden comment: GRM188R71E105KA12D)
C80  ValueDisplayed: 1µF  [0603]  (hidden comment: GRM188R71E105KA12D)
C81  ValueDisplayed: 10µF  [0805_HV]  (hidden comment: GRM21BR71A106KE51L)
C88  ValueDisplayed: 10µF  [0805]  (hidden comment: GRM21BR71A106KE51L)
C197  ValueDisplayed: 1µF  [0603]  (hidden comment: GRM188R71A105KA61D)
C231  ValueDisplayed: 0.1µF  [0402]  (hidden comment: GRM155R71C104KA88D)
C232  ValueDisplayed: 0.1µF  [0603]  (hidden comment: C0603C104J3RACTU)
C233  ValueDisplayed: 10µF  [0603_120]  (hidden comment: ZRB18AD71A106KE01L)
C234  ValueDisplayed: 0.1µF  [0402]  (hidden comment: GRM155R61E104KA87D)
C235  ValueDisplayed: 0.1µF  [0402]  (hidden comment: GRM155R61E104KA87D)
D4  CUS05S40,H3F  [sod-323]
J10  87898-0204  [Molex_87898-0204]
J11  87898-0204  [Molex_87898-0204]
R46  value 0.22  [0603]  (hidden comment: ERJ-3RQFR22V)
R47  value 0.22  [0603]  (hidden comment: ERJ-3RQFR22V)
R48  ValueDisplayed: 0  [0603]  (hidden comment: ERJ-3GEY0R00V)
R49  ValueDisplayed: 0  [0603]  (hidden comment: ERJ-3GEY0R00V)
R85  ValueDisplayed: 1.00k  [0603]  (hidden comment: RG1608P-102-B-T5)
R86  ValueDisplayed: 2.49k  [0603]  (hidden comment: RG1608P-2491-B-T5)
R88  ValueDisplayed: 4.99k  [0603]  (hidden comment: RG1608P-4991-B-T5)
R89  ValueDisplayed: 4.75  [0603]  (hidden comment: CRCW06034R75FKEA)
R91  ValueDisplayed: 1.00k  [0603]  (hidden comment: RG1608P-102-B-T5)
R92  ValueDisplayed: 499  [0603]  (hidden comment: RG1608P-4990-B-T5)
R94  ValueDisplayed: 30.0k  [0603]  (hidden comment: RG1608P-303-B-T5)
R106  ValueDisplayed: 20.0k  [0603]  (hidden comment: RG1608P-203-B-T5)
R109  ValueDisplayed: 280k  [0805_HV]  (hidden comment: RG2012P-2803-B-T5)
R110  ValueDisplayed: 499  [0603]  (hidden comment: RG1608P-4990-B-T5)
R111  ValueDisplayed: 20.0k  [0603]  (hidden comment: RG1608P-203-B-T5)
R112  ValueDisplayed: 10.0k  [0603]  (hidden comment: RG1608P-103-B-T5)
R113  ValueDisplayed: 0.22  [0603]  (hidden comment: ERJ-3RQFR22V)
R114  ValueDisplayed: 20.0k  [0603]  (hidden comment: RG1608P-203-B-T5)
R267  ValueDisplayed: 4.7k  [0402]  (hidden comment: CRCW04024K70JNED)
R268  ValueDisplayed: 0.1  [0402]  (hidden comment: ERJ-2BSFR10X)
R269  ValueDisplayed: 33  [0402]  (hidden comment: CRCW040233R0JNED)
R270  ValueDisplayed: 4.7k  [0402]  (hidden comment: CRCW04024K70JNED)
R271  ValueDisplayed: 4.7k  [0402]  (hidden comment: CRCW04024K70JNED)
R273  ValueDisplayed: 33  [0402]  (hidden comment: CRCW040233R0JNED)
R274  ValueDisplayed: 100  [0402]  (hidden comment: CRCW0402100RJNED)
R276  ValueDisplayed: 0.1  [0402]  (hidden comment: ERJ-2BSFR10X)
R277  ValueDisplayed: 4.7k  [0402]  (hidden comment: CRCW04024K70JNED)
U14  OPA378AIDBVT  [DBV0005A_N]
U15  OPA625IDBVR  [DBV0006A_N]
U22  REF5045AIDGKT  [DGK0008A_N]  (part A of 2)
U23  OPA376AIDBVR  [DBV0005A_N]
U34  REF6041AIDGK  [DGK0008A_N]
U36  LMK61E2-SIAR  [SIA0008B]
U37  SN65LVDS4RSET  [RSE0010A]

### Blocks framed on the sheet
REF6041: C1 C88 C197 R46 R47 U34
COMMON MODE REFERENCE GENERATION: C74 C77 C80 J10 J11 R106 R109-R112 R114 U23

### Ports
ISO_SCL (bidir), ISO_SDA (bidir)

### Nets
1P8V_ISO: C59.1 U37.5(VCC)
3P3V_ISO: C231.1 C232.1 C233.1 R270.2 R271.2 R277.1 U36.1(OE) U36.6(VDD) U37.10(VDD)
5V_ISO: C49.2 C55.2 C77.2 C79.1 C88.2 D4.1(K) U14.5(V+) U15.6(V+) U22.2(VIN) U23.5(V+) U34.1(VIN) U34.2(EN)
AGND_ISO: C49.1 C53.2 C54.2 C55.1 C57.2 C58.2 C59.2 C77.1 C79.2 C80.2 C81.2 C88.1 C197.2 C231.2 C232.2 C233.2 J11.2 R46.2 R47.1 R88.1 R91.1 R114.1 R267.1 U14.2(V-) U15.2(V-) U15.5(MODE) U22.4(GND) U23.2(V-) U34.7(GND_F) U34.8(GND_S) U36.3(GND) U37.1(GND) U37.7(GND)
BCLK_ISO: R269.2 ; off-sheet BCLK_ISO
BCLK_N: C235.1 U36.5(OUTN) ; off-sheet BCLK_N
BCLK_P: C234.1 U36.4(OUTP) ; off-sheet BCLK_P
ISO_SCL: R271.1 U36.8(SCL) ; port ISO_SCL
ISO_SDA: R270.1 U36.7(SDA) ; port ISO_SDA
MCLK: R273.2 ; off-sheet MCLK
OPA625_CM: R106.2 R110.2 ; off-sheet OPA625_CM
REF5045_BUF: C52.1 C61.1 D4.2(A) R49.2 R89.2 R92.2 R94.2
REF6045_BUF: C1.2 R48.2 U34.5(OUT_S) U34.6(OUT_F)
REFBUF: R48.1 R49.1 R268.2 R276.2 ; off-sheet REFBUF
REFOUT: J10.1 R85.1 R111.1 R113.2 U22.6(VOUT) ; off-sheet REFOUT
NetC1_1: C1.1 R46.1
NetC52_2: C52.2 R89.1 U15.1(OUT)
NetC53_1: C53.1 R85.2 U14.3(IN+)
NetC54_1: C54.1 R86.2 R88.2 U15.3(IN+)
NetC57_1: C57.1 R276.1
NetC58_1: C58.1 R268.1
NetC60_1: C60.1 R86.1 U14.1(OUT)
NetC60_2: C60.2 R94.1 U14.4(IN-)
NetC61_2: C61.2 R91.2 R92.1 U15.4(IN-)
NetC74_1: C74.1 R110.1 U23.1(OUT)
NetC74_2: C74.2 R106.1 U23.4(IN-)
NetC80_1: C80.1 R109.2 R111.2 R112.2 R114.2 U23.3(IN+)
NetC81_1: C81.1 R113.1
NetC197_1: C197.1 U34.4(SS)
NetC234_2: C234.2 R274.2 U37.3(B)
NetC235_2: C235.2 R274.1 U37.2(A)
NetJ10_2: J10.2 R109.1
NetJ11_1: J11.1 R112.1
NetR47_2: R47.2 U34.3(FILT)
NetR267_2: R267.2 R277.2 U36.2(ADD)
NetR269_1: R269.1 R273.1 U37.8(R)

Not connected (* = marked no-connect by the designer): U22 3(TEMP) 5(TRIM/NR); U37 4(NC) 6(NC) 9(NC)

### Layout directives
differential pair: BCLK_N, BCLK_P, NetC234_2, NetC235_2

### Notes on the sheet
- REF5045
- PROG MASTER CLOCK GENERATION

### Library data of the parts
C1 = GRM32ER71A476KE15L: CAP, CERM, 47 µF, 10 V, +/- 10%, X7R, 1210; Manufacturer: MuRata; Polarized: N; CompType: Capacitor; Value: 47uF; U/M: EA; Cap_F: 0.000047; Tolerance_%: 10; Value1: Unknown; Value2: 10V; TaMin_C: -55; TaMax_C: 125
C49 C233 = ZRB18AD71A106KE01L: CAP, CERM, 10 µF, 10 V, +/- 10%, X7T, 0603; Manufacturer: MuRata; Polarized: N; CompType: Capacitor; Value: 10uF; U/M: EA; Cap_F: 0.00001; Tolerance_%: 10; Value1: Unknown; Value2: 10V; TaMin_C: -55; TaMax_C: 125; Cap_Case: 0603; AEC Category: Q200
C52 = 0805YC224JAT2A: CAP, CERM, 0.22 µF, 16 V, +/- 5%, X7R, 0805; Manufacturer: AVX; Polarized: N; CompType: Capacitor; Value: 0.22uF; U/M: EA; Cap_F: 0.00000022; Tolerance_%: 5; ESR_ohm: 0.016; Value1: 0.016 ohm; VDC_V: 16; Value2: 16V; TaMin_C: -55; TaMax_C: 125; Cap_Case: 0805
C53 C79 = GRM188R71E105KA12D: CAP, CERM, 1 µF, 25 V, +/- 10%, X7R, 0603; Manufacturer: MuRata; Polarized: N; CompType: Capacitor; Value: 1uF; U/M: EA; Cap_F: 0.000001; Tolerance_%: 10; Value1: Unknown; VDC_V: 25; Value2: 25V; TaMin_C: -55; TaMax_C: 125
C54 C55 C60 C232 = C0603C104J3RACTU: CAP, CERM, 0.1 µF, 25 V, +/- 5%, X7R, 0603; Manufacturer: Kemet; Polarized: N; CompType: Capacitor; Value: 0.1uF; U/M: EA; Cap_F: 0.0000001; Tolerance_%: 5; Value1: Unknown; VDC_V: 25; Value2: 25V; TaMin_C: -55; TaMax_C: 125
C57 C58 = GRM188R60J226MEA0J: CAP, CERM, 22 µF, 6.3 V, +/- 20%, X5R, 0603; Manufacturer: MuRata; Polarized: N; CompType: Capacitor; Value: 22uF; U/M: EA; Cap_F: 0.000022; Tolerance_%: 20; Value1: Unknown; VDC_V: 6.3; Value2: 6.3V; TaMin_C: -55; TaMax_C: 85; AEC Category: Q200
C59 C231 = GRM155R71C104KA88D: CAP, CERM, 0.1 µF, 16 V, +/- 10%, X7R, 0402; Manufacturer: MuRata; Polarized: N; CompType: Capacitor; Value: 0.1uF; U/M: EA; Cap_F: 0.0000001; Tolerance_%: 10; Value1: Unknown; VDC_V: 16; Value2: 16V; TaMin_C: -55; TaMax_C: 125
C61 = C0603C100F5GAC7867: CAP, CERM, 10 pF, 50 V, +/- 1%, C0G/NP0, 0603; Manufacturer: Kemet; Polarized: N; CompType: Capacitor; Value: 10pF; U/M: EA; Cap_F: 0.00000000001; Tolerance_%: 1; Value1: Unknown; VDC_V: 50; Value2: 50V; TaMin_C: -55; TaMax_C: 125; AEC Category: Q200
C74 C80 = GRM188R71E105KA12D: as C24 on sheet TIDA-00732_Pwr
C77 = C0603C104J3RACTU: CAP, CERM, 0.1 µF, 25 V, +/- 5%, X7R, 0603; Manufacturer: Kemet; Polarized: N; CompType: Capacitor; Value: 0.1uF; U/M: EA; Cap_F: 0.0000001; Tolerance_%: 5; Value1: Unknown; VDC_V: 25; Value2: 25V; TaMin_C: -55; TaMax_C: 125; AEC Category: Q200
C81 = GRM21BR71A106KE51L: CAP, CERM, 10 µF, 10 V, +/- 10%, X7R, 0805; Manufacturer: MuRata; Polarized: N; CompType: Capacitor; Value: 10uF; U/M: EA; Cap_F: 0.00001; Tolerance_%: 10; ESR_ohm: 0.003; Value1: 0.003 ohm; Value2: 10V; TaMin_C: -55; TaMax_C: 125; Cap_Case: 0805
C88 = GRM21BR71A106KE51L: CAP, CERM, 10uF, 10V, +/-10%, X7R, 0805; Manufacturer: MuRata; Polarized: N; CompType: Capacitor; U/M: EA; Cap_F: 0.00001; Tolerance_%: 10; ESR_Ohm: 0.003; Value1: 0.003 ohm; TaMin_C: -55; TaMax_C: 125
C197 = GRM188R71A105KA61D: CAP, CERM, 1uF, 10V, +/-10%, X7R, 0603; Manufacturer: MuRata; Polarized: N; CompType: Capacitor; U/M: EA; Cap_F: 0.000001; Tolerance_%: 10; ESR_Ohm: 0.011; Value1: 0.011 ohm; TaMin_C: -55; TaMax_C: 125
C234 C235 = GRM155R61E104KA87D: CAP, CERM, 0.1 µF, 25 V, +/- 10%, X5R, 0402; Manufacturer: MuRata; Polarized: N; CompType: Capacitor; Value: 0.1uF; U/M: EA; Cap_F: 0.0000001; Tolerance_%: 10; Value1: Unknown; VDC_V: 25; Value2: 25V; TaMin_C: -55; TaMax_C: 85; AEC Category: Q200
D4 = CUS05S40,H3F: Diode, Schottky, 40 V, 0.5 A, SOD-323; Manufacturer: Toshiba; U/M: EA; Vf_V: 0.6; Value: 40V; Value1: 0.5A; Value2: 0.6V; Io_A: 0.5; Vr_V: 40; TJmax_C: 125; AEC Category: Q101; AEC Qualified: N
J10 J11 = 87898-0204: Header, 2.54 mm, 2x1, Gold, R/A, SMT; Manufacturer: Molex; SymbolCreator: a0412235; U/M: EA
R46 R47 = ERJ-3RQFR22V: RES, 0.22 ohm, 1%, 0.1W, 0603; Manufacturer: Panasonic; CompType: Resistor; Value_Code: R220; Tolerance_%: 1; Power_W: 0.1; TempCo: 300 ppm/C; EIA_Code: E96; U/M: EA
R48 R49 = ERJ-3GEY0R00V: RES, 0, 5%, 0.1 W, 0603; Manufacturer: Panasonic; CompType: Resistor; Value: 0; Value_Code: 0000; Tolerance_%: 5; Power_W: 0.1; Value2: 0.1W; VDC_V: 50; TempCo: 600 ppm/C; EIA_Code: E24; U/M: EA; AEC Category: Q200
R85 R91 = RG1608P-102-B-T5: RES, 1.00 k, 0.1%, 0.1 W, 0603; Manufacturer: Susumu Co Ltd; CompType: Resistor; Value: 1.00k; Res_ohm: 1000; Value_Code: 1k00; Tolerance_%: 0.1; Value2: 0.1W; VDC_V: 75; TempCo: 25 ppm/C; EIA_Code: E192; U/M: EA
R86 = RG1608P-2491-B-T5: RES, 2.49 k, 0.1%, 0.1 W, 0603; Manufacturer: Susumu Co Ltd; CompType: Resistor; Value: 2.49k; Res_ohm: 2490; Value_Code: 2k49; Tolerance_%: 0.1; Value2: 0.1W; VDC_V: 75; TempCo: 25 ppm/C; EIA_Code: E192; U/M: EA
R88 = RG1608P-4991-B-T5: RES, 4.99 k, 0.1%, 0.1 W, 0603; Manufacturer: Susumu Co Ltd; CompType: Resistor; Value: 4.99k; Res_ohm: 4990; Value_Code: 4k99; Tolerance_%: 0.1; Value2: 0.1W; VDC_V: 75; TempCo: 25 ppm/C; EIA_Code: E192; U/M: EA
R89 = CRCW06034R75FKEA: RES, 4.75, 1%, 0.1 W, 0603; Manufacturer: Vishay-Dale; CompType: Resistor; Value: 4.75; Value_Code: 4R75; Tolerance_%: 1; Power_W: 0.1; Value2: 0.1W; VDC_V: 75; TempCo: 100 ppm/C; EIA_Code: E96; U/M: EA
R92 = RG1608P-4990-B-T5: RES, 499, 0.1%, 0.1 W, 0603; Manufacturer: Susumu Co Ltd; CompType: Resistor; Value: 499; Value_Code: 499R; Tolerance_%: 0.1; Value2: 0.1W; VDC_V: 75; TempCo: 25 ppm/C; EIA_Code: E192; U/M: EA
R94 = RG1608P-303-B-T5: RES, 30.0 k, 0.1%, 0.1 W, 0603; Manufacturer: Susumu Co Ltd; CompType: Resistor; Value: 30.0k; Res_ohm: 30000; Value_Code: 30k0; Tolerance_%: 0.1; Value2: 0.1W; VDC_V: 75; TempCo: 25 ppm/C; U/M: EA; AEC Category: Q200
R106 R111 R114 = RG1608P-203-B-T5: RES, 20.0 k, 0.1%, 0.1 W, 0603; Manufacturer: Susumu Co Ltd; CompType: Resistor; Value: 20.0k; Res_ohm: 20000; Value_Code: 20k0; Tolerance_%: 0.1; Value2: 0.1W; VDC_V: 75; TempCo: 25 ppm/C; EIA_Code: E192; U/M: EA; AEC Category: Q200
R109 = RG2012P-2803-B-T5: RES, 280 k, 0.1%, 0.125 W, 0805; Manufacturer: Susumu Co Ltd; CompType: Resistor; Value: 280k; Res_ohm: 280000; Tolerance_%: 0.1; Power_W: 0.125; Value2: 0.125W; VDC_V: 100; TempCo: 25 ppm/C; EIA_Code: E192; U/M: EA; AEC Category: Q200
R110 = RG1608P-4990-B-T5: RES, 499, 0.1%, 0.1 W, 0603; Manufacturer: Susumu Co Ltd; CompType: Resistor; Value: 499; Value_Code: 499R; Tolerance_%: 0.1; Value2: 0.1W; VDC_V: 75; TempCo: 25 ppm/C; EIA_Code: E192; U/M: EA; AEC Category: Q200
R112 = RG1608P-103-B-T5: as R249 on sheet TIDA-00732_Pwr_Sense
R113 = ERJ-3RQFR22V: RES, 0.22, 1%, 0.1 W, 0603; Manufacturer: Panasonic; CompType: Resistor; Value: 0.22; Value_Code: R220; Tolerance_%: 1; Power_W: 0.1; Value2: 0.1W; TempCo: 300 ppm/C; EIA_Code: E96; U/M: EA
R267 R270 R271 R277 = CRCW04024K70JNED: RES, 4.7 k, 5%, 0.063 W, 0402; Manufacturer: Vishay-Dale; CompType: Resistor; Value: 4.7k; Res_ohm: 4700; Value_Code: 4k70; Tolerance_%: 5; Power_W: 0.063; Value2: 0.063W; VDC_V: 50; TempCo: 200 ppm/C; EIA_Code: E24; U/M: EA; AEC Category: Q200
R268 R276 = ERJ-2BSFR10X: RES, 0.1, 1%, 0.125 W, 0402; Manufacturer: Panasonic; CompType: Resistor; Value: 0.1; Value_Code: R100; Tolerance_%: 1; Power_W: 0.125; Value2: 0.125W; TempCo: 300 ppm/C; EIA_Code: E96; U/M: EA; AEC Category: Q200
R269 R273 = CRCW040233R0JNED: RES, 33, 5%, 0.063 W, 0402; Manufacturer: Vishay-Dale; CompType: Resistor; Value: 33; Value_Code: 33R0; Tolerance_%: 5; Power_W: 0.063; Value2: 0.063W; VDC_V: 50; TempCo: 200 ppm/C; EIA_Code: E24; U/M: EA; AEC Category: Q200
R274 = CRCW0402100RJNED: RES, 100, 5%, 0.063 W, 0402; Manufacturer: Vishay-Dale; CompType: Resistor; Value: 100; Value_Code: 100R; Tolerance_%: 5; Power_W: 0.063; Value2: 0.063W; VDC_V: 50; TempCo: 200 ppm/C; EIA_Code: E24; U/M: EA; AEC Category: Q200
U14 = OPA378AIDBVT: Low-Noise, 900 kHz, RRIO, Precision Operational Amplifier, Zerø-Drift Series, 2.2 to 5.5 V, -40 to 125 degC, 5-pin SOT23 (DBV0005A), Green (RoHS & no Sb/Br); Manufacturer: Texas Instruments; Alternate PartNumber: Equivalent; CMRR(Min)(dB): 100; IIB(Max)(pA): 550; Iq per channel(Max)(mA): 0.15; Number of Channels: 1; Offset Drift(Typ)(uV/C): 0.1; Slew Rate(Typ)(V/us): 0.4; Sub Family: Low Input Bias Current Amp (<=10pA), Low Offset Voltage Amplifier (<=500uV), Low Power Amp (<=500uA), Low Supply Voltage Amplifier (<=2.7V), Precision Amplifier, Zero Drift Precision Amplifier; Total Supply Voltage(Max)(+5V is 5, +/-5V is 10): 5.5; Total Supply Voltage(Min)(+5V is 5, +/-5V is 10): 2.2; Vio (25C)(Max)(mV): 0.05; Vn at 1kHz(Typ)(nV/rtHz): 20
U15 = OPA625IDBVR: High-Bandwidth, High-Precision, Low THD+N, 16-Bit and 18-Bit Analog-to-Digital Converter (ADC) Drivers, DBV0006A; Alternate PartNumber: OPA625IDBVT; Manufacturer: Texas Instruments; SymbolCreator: Altium; CompType: IC; U/M: EA
U22 = REF5045AIDGKT: Low Noise, Very Low Drift, Precision Voltage Reference, -40 to 125 degC, 8-pin MSOP (DGK), Green (RoHS & no Sb/Br); Manufacturer: Texas Instruments; Alternate PartNumber: Equivalent; Initial Accuracy @ 25/deg C(%): 0.05; Iout/Iz(Max)(mA): 10; Iq(Max)(uA): 1000; Rating: Catalog; SubFamily: Series Voltage Reference; Temp Coeff(Max)(ppm/ degree C): 3; VI(Max)(V): 18; VI(Min)(V): 4.7; VO(V): 4.5
U23 = OPA376AIDBVR: Precision, Low Noise, Low Iq Operational Amplifier, 2.2 to 5.5 V, -40 to 125 degC, 5-pin SOT23 (DBV0005A), Green (RoHS & no Sb/Br); Manufacturer: Texas Instruments; Alternate PartNumber: Equivalent; CMRR(Min)(dB): 76; IIB(Max)(pA): 10; Iq per channel(Max)(mA): 0.95; Number of Channels: 1; Offset Drift(Typ)(uV/C): 0.32; Slew Rate(Typ)(V/us): 2; Sub Family: Low Input Bias Current Amp (<=10pA), Low Noise Amp (<=10nV/rtHz), Low Offset Voltage Amplifier (<=500uV), Low Supply Voltage Amplifier (<=2.7V), Precision Amplifier; Total Supply Voltage(Max)(+5V is 5, +/-5V is 10): 5.5; Total Supply Voltage(Min)(+5V is 5, +/-5V is 10): 2.2; Vio (25C)(Max)(mV): 0.025; Vn at 1kHz(Typ)(nV/rtHz): 7.5
U34 = REF6025AIDGK: High-Precision Voltage Reference with Integrated High-Bandwidth Buffer, DGK0008A; Manufacturer: Texas Instruments; SymbolCreator: Altium; CompType: IC; U/M: EA
U36 = LMK61E2-SIAR: Ultra-Low Jitter Programmable Oscillator with Internal EEPROM, SIA0008B; Alternate PartNumber: LMK61E2-SIAT; Manufacturer: Texas Instruments; SymbolCreator: Altium; CompType: IC; U/M: EA
U37 = SN65LVDS4RSET: 500 Mbps High-Speed Differential Line Driver / Receivers with LVDS Input and LVTTL / LVCMOS Output, 1 Rx, -40 to +85 degC, 10-pin UQFN (RSE), Green (RoHS & no Sb/Br); Manufacturer: Texas Instruments; Alternate PartNumber: Equivalent; ESD HBM(kV): 2; Function: Transceiver; No. of Rx: 1; No. of Tx: 0; Output Signal: LVTTL, LVCMOS; Signaling Rate(Mbps): 500; SubFamily: LVDS PHY (<800Mbps)

## Sheet TIDA-00732_TID_Hardware.SchDoc: Fastners
size 431 x 279 mm; Date: Not shown in title block; ApprovedBy: Not shown in title block; CheckedBy: Not shown in title block; Author: Not shown in title block; CompanyName: Not shown in title block; DrawnBy: Anbu Mani; Engineer: Not shown in title block; Organization: Not shown in title block; Address1: Not shown in title block; Address2: Not shown in title block; Address3: Not shown in title block; Address4: Not shown in title block; DocumentNumber: 1; Revision: Use project parameter SCH_Rev; SheetNumber: 10; SheetTotal: 10; PageSetup: Record=PageOptions¦CenterHorizontal=True¦CenterVertical=True¦PrintScale=1.00¦XCorrection=1.00¦YCorrection=1.00¦PrintKind=0¦BorderSize=5000000¦LeftOffset=0¦BottomOffset=0¦Orientation=2¦PaperLength=1000¦PaperWidth=1000¦Scale=100¦PaperSource=15¦PrintQuality=600¦MediaType=1¦DitherType=10¦PaperKind=Letter¦PrintScaleMode=1
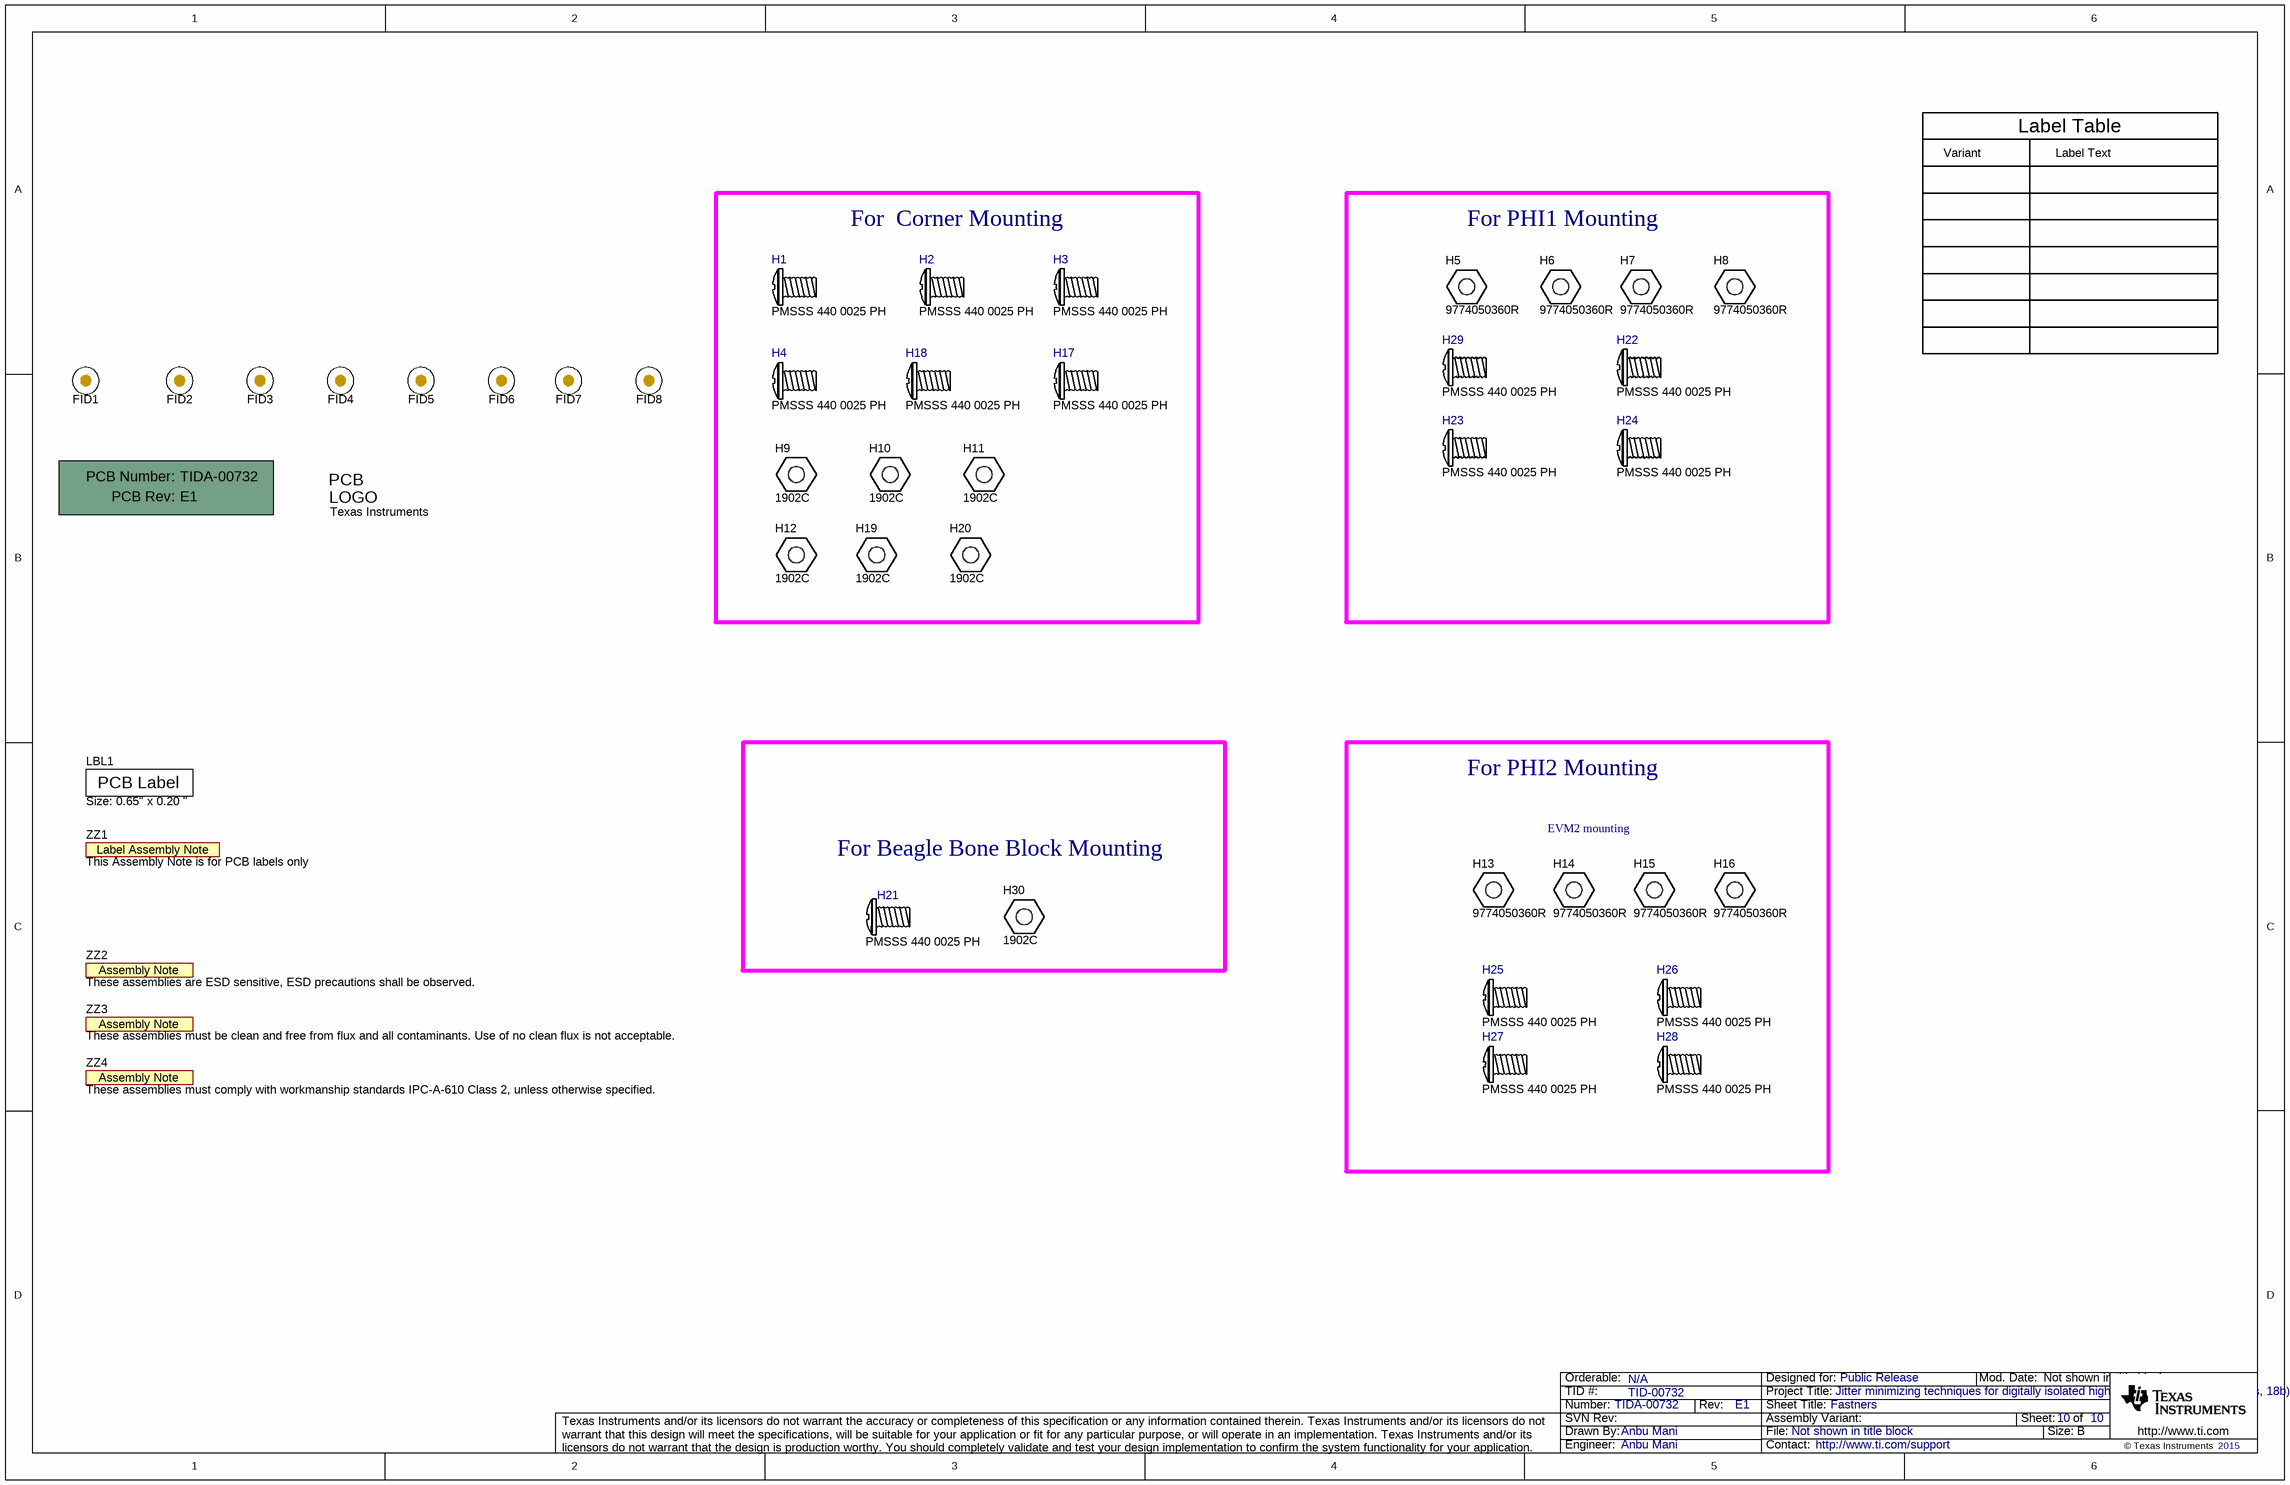
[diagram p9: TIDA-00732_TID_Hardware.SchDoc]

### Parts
!PCB1  Printed Circuit Board  (value not drawn)  (mechanical)
FID1  Fiducial  [Fiducial10-20]  (value not drawn)
FID2  Fiducial  [Fiducial10-20]  (value not drawn)
FID3  Fiducial  [Fiducial10-20]  (value not drawn)
FID4  Fiducial  [Fiducial10-20]  (value not drawn)
FID5  Fiducial  [Fiducial10-20]  (value not drawn)
FID6  Fiducial  [Fiducial10-20]  (value not drawn)
FID7  Fiducial  [Fiducial10-20]  (value not drawn)
FID8  Fiducial  [Fiducial10-20]  (value not drawn)
H1  PMSSS 440 0025 PH  [B_F_PMSSS4400025PH]
H2  PMSSS 440 0025 PH  [B_F_PMSSS4400025PH]
H3  PMSSS 440 0025 PH  [B_F_PMSSS4400025PH]
H4  PMSSS 440 0025 PH  [B_F_PMSSS4400025PH]
H5  9774050360R  [Wurth_WA-SMSI]
H6  9774050360R  [Wurth_WA-SMSI]
H7  9774050360R  [Wurth_WA-SMSI]
H8  9774050360R  [Wurth_WA-SMSI]
H9  1902C  [Keystone_1902C]
H10  1902C  [Keystone_1902C]
H11  1902C  [Keystone_1902C]
H12  1902C  [Keystone_1902C]
H13  9774050360R  [Wurth_WA-SMSI]
H14  9774050360R  [Wurth_WA-SMSI]
H15  9774050360R  [Wurth_WA-SMSI]
H16  9774050360R  [Wurth_WA-SMSI]
H17  PMSSS 440 0025 PH  [B_F_PMSSS4400025PH]
H18  PMSSS 440 0025 PH  [B_F_PMSSS4400025PH]
H19  1902C  [Keystone_1902C]
H20  1902C  [Keystone_1902C]
H21  PMSSS 440 0025 PH  [B_F_PMSSS4400025PH]
H22  PMSSS 440 0025 PH  [B_F_PMSSS4400025PH]  (mechanical)
H23  PMSSS 440 0025 PH  [B_F_PMSSS4400025PH]  (mechanical)
H24  PMSSS 440 0025 PH  [B_F_PMSSS4400025PH]  (mechanical)
H25  PMSSS 440 0025 PH  [B_F_PMSSS4400025PH]  (mechanical)
H26  PMSSS 440 0025 PH  [B_F_PMSSS4400025PH]  (mechanical)
H27  PMSSS 440 0025 PH  [B_F_PMSSS4400025PH]  (mechanical)
H28  PMSSS 440 0025 PH  [B_F_PMSSS4400025PH]  (mechanical)
H29  PMSSS 440 0025 PH  [B_F_PMSSS4400025PH]  (mechanical)
H30  1902C  [Keystone_1902C]
LBL1  Size: 0.65" x 0.20 "  [Label_650x200]
Logo1  Texas Instruments  [TI_Stacked_Overlay_Small]  (no BOM)
ZZ1  This Assembly Note is for PCB labels only  [AssemblyNoteLabel]  (no BOM)
ZZ2  These assemblies are ESD sensitive, ESD precautions shall be observed.  [AssemblyNote]  (no BOM)
ZZ3  These assemblies must be clean and free from flux and all contaminants. Use of no clean flux is not acceptable.  [AssemblyNote]  (no BOM)
ZZ4  These assemblies must comply with workmanship standards IPC-A-610 Class 2, unless otherwise specified.  [AssemblyNote]  (no BOM)

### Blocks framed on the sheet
For  Corner Mounting: H1-H4 H9-H12 H17-H20
For PHI1 Mounting: H5-H8 H22-H24 H29
For Beagle Bone Block Mounting: H21 H30
For PHI2 Mounting: H13-H16 H25-H28

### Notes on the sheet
- Variant
- Label Table
- Label Text
- EVM2 mounting

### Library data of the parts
!PCB1 = PCB: Manufacturer: Any; PartNumber: TIDA-00732; SymbolCreator: a0412235
FID1-FID8 = Fiducial: Fiducial mark.  There is nothing to buy or mount.; SymbolCreator: codlsc
H1-H4 H17 H18 H21-H29 = PMSSS 440 0025 PH: MACHINE SCREW PAN PHILLIPS 4-40; Manufacturer: B&F Fastener Supply; CompType: Standoff; SymbolCreator: a0412235
H5-H8 H13-H16 = 9774050360R: ROUND STANDOFF M3 STEEL 11MM; Manufacturer: Wurth Elektronik; SymbolCreator: a0412235
H9-H12 H19 H20 H30 = 1902C: Standoff, Hex, 0.5"L #4-40 Nylon; Manufacturer: Keystone; CompType: Hardware
LBL1 = THT-14-423-10: Thermal Transfer Printable Labels, 0.650" W x 0.200" H - 10,000 per roll; Manufacturer: Brady; SymbolCreator: a0412235; CompType: Label
Logo1 = TI_Logo: Texas Instrument Corporate Signature; SymbolCreator: codlsc
ZZ1 = AssemblyNoteLabel: SymbolCreator: a0412235
ZZ2-ZZ4 = AssemblyNote: SymbolCreator: codlsc

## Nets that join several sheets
1P2V: TIDA-00732_Isolator (TP46.1), TIDA-00732_FPGA_2 (14 pins), TIDA-00732_Pwr (5 pins)
1P2V_ISO: TIDA-00732_Isolator (TP43.1), TIDA-00732_FPGA_1 (14 pins), TIDA-00732_Pwr (5 pins)
1P8V: TIDA-00732_Isolator (TP45.1), TIDA-00732_FPGA_2 (12 pins), TIDA-00732_Pwr (J17.2 R241.2)
1P8V_ISO: TIDA-00732_Isolator (TP47.1), TIDA-00732_ADC (7 pins), TIDA-00732_FPGA_1 (13 pins), TIDA-00732_Pwr (J13.2 R242.2), TIDA-00732_ADC_Ref_Select (C59.1 U37.5)
3P3V: TIDA-00732_Isolator (14 pins), TIDA-00732_FPGA_2 (71 pins), TIDA-00732_Pwr (8 pins)
3P3V_ISO: TIDA-00732_Isolator (14 pins), TIDA-00732_ADC (C50.2 R87.2 U16.5), TIDA-00732_FPGA_1 (62 pins), TIDA-00732_Pwr (9 pins), TIDA-00732_ADC_Ref_Select (9 pins)
5V_ISO: TIDA-00732_Isolator (TP40.1), TIDA-00732_ADC (5 pins), TIDA-00732_Pwr (J12.2), TIDA-00732_ADC_Ref_Select (12 pins)
5V_ISO1: TIDA-00732_Isolator (5 pins), TIDA-00732_Pwr (J12.3)
5VDC: TIDA-00732_Connector (L1.1), TIDA-00732_Isolator (7 pins), TIDA-00732_Pwr (13 pins), TIDA-00732_Pwr_Sense (R254.2 R255.2)
A1P8V_ISO: TIDA-00732_Isolator (TP41.1), TIDA-00732_ADC (R208.1), TIDA-00732_Pwr (5 pins)
AGND_ISO: TIDA-00732_Connector (14 pins), TIDA-00732_Isolator (36 pins), TIDA-00732_ADC (40 pins), TIDA-00732_FPGA_1 (82 pins), TIDA-00732_Pwr (33 pins), TIDA-00732_Pwr_Sense (12 pins), TIDA-00732_ADC_Ref_Select (33 pins)
EVM1_DVDD: TIDA-00732_Connector (C83.1 J3.50), TIDA-00732_Pwr (J13.1), TIDA-00732_Pwr_Sense (R252.2)
EVM1_ID_PWR: TIDA-00732_Connector (6 pins), TIDA-00732_Pwr_Sense (6 pins)
EVM1_REG_5V5: TIDA-00732_Connector (C82.1 J3.1), TIDA-00732_Pwr (J12.1)
EVM2_DVDD: TIDA-00732_Connector (C89.1 J18.50), TIDA-00732_Pwr (J17.1), TIDA-00732_Pwr_Sense (R258.2)
EVM2_ID_PWR: TIDA-00732_Connector (6 pins), TIDA-00732_Pwr_Sense (6 pins)
GND: TIDA-00732_Connector (22 pins), TIDA-00732_Isolator (30 pins), TIDA-00732_FPGA_2 (80 pins), TIDA-00732_Pwr (27 pins), TIDA-00732_Pwr_Sense (11 pins)
LDO_IN_ISO: TIDA-00732_Isolator (8 pins), TIDA-00732_Pwr (17 pins), TIDA-00732_Pwr_Sense (R247.2 R248.2)
ADC_CONVST: TIDA-00732_ADC (R45.2 U33.1), TIDA-00732_FPGA_1 (U24.129)
ADC_CONVST1: TIDA-00732_Isolator (R207.2), TIDA-00732_FPGA_1 (U24.57)
ADC_CONVST_FPGA: TIDA-00732_Isolator (R260.1), TIDA-00732_FPGA_2 (U25.140)
ADC_CSn: TIDA-00732_ADC (U19.24), TIDA-00732_FPGA_1 (U24.130)
ADC_MRESETn: TIDA-00732_ADC (U16.4 U17.1), TIDA-00732_FPGA_1 (U24.72)
ADC_RVS: TIDA-00732_ADC (U19.21), TIDA-00732_FPGA_1 (U24.134)
ADC_SCLK: TIDA-00732_ADC (U19.23), TIDA-00732_FPGA_1 (U24.131)
ADC_SDI: TIDA-00732_ADC (U19.22), TIDA-00732_FPGA_1 (U24.132)
ADC_SDO0: TIDA-00732_ADC (U19.20), TIDA-00732_FPGA_1 (U24.135)
ADC_SDO1: TIDA-00732_ADC (U19.19), TIDA-00732_FPGA_1 (U24.138)
ADC_SDO2: TIDA-00732_ADC (U19.18), TIDA-00732_FPGA_1 (U24.139)
ADC_SDO3: TIDA-00732_ADC (U19.17), TIDA-00732_FPGA_1 (U24.141)
ADC_SRESETn: TIDA-00732_ADC (R93.1 U17.2), TIDA-00732_FPGA_1 (U24.110)
BBB_ADC_CSn: TIDA-00732_Connector (R41.1), TIDA-00732_FPGA_2 (U25.12)
BBB_ADC_RESETn: TIDA-00732_Connector (R37.1), TIDA-00732_FPGA_2 (U25.18)
BBB_ADC_RVS: TIDA-00732_Connector (R36.2), TIDA-00732_FPGA_2 (U25.20)
BBB_ADC_SCLK: TIDA-00732_Connector (R43.1), TIDA-00732_FPGA_2 (U25.13)
BBB_ADC_SDI: TIDA-00732_Connector (R39.1), TIDA-00732_FPGA_2 (U25.15)
BBB_ADC_SDO0: TIDA-00732_Connector (R38.2), TIDA-00732_FPGA_2 (U25.19)
BBB_ADC_SDO1: TIDA-00732_Connector (R40.2), TIDA-00732_FPGA_2 (U25.16)
BBB_ADC_SDO2: TIDA-00732_Connector (R42.2), TIDA-00732_FPGA_2 (U25.10)
BBB_ADC_SDO3: TIDA-00732_Connector (R44.2), TIDA-00732_FPGA_2 (U25.11)
BBB_GPI0: TIDA-00732_Connector (R138.2), TIDA-00732_FPGA_2 (U25.102)
BBB_GPIO0: TIDA-00732_Connector (R1.1), TIDA-00732_FPGA_2 (U25.71)
BBB_GPIO1: TIDA-00732_Connector (R3.1), TIDA-00732_FPGA_2 (U25.69)
BBB_GPIO2: TIDA-00732_Connector (R5.1), TIDA-00732_FPGA_2 (U25.64)
BBB_GPIO3: TIDA-00732_Connector (R7.1), TIDA-00732_FPGA_2 (U25.60)
BBB_GPIO4: TIDA-00732_Connector (R11.1), TIDA-00732_FPGA_2 (U25.54)
BBB_GPIO5: TIDA-00732_Connector (R13.1), TIDA-00732_FPGA_2 (U25.50)
BBB_GPIO6: TIDA-00732_Connector (R15.1), TIDA-00732_FPGA_2 (U25.48)
BBB_GPIO7: TIDA-00732_Connector (R17.1), TIDA-00732_FPGA_2 (U25.46)
BBB_GPIO8: TIDA-00732_Connector (R19.1), TIDA-00732_FPGA_2 (U25.31)
BBB_GPIO9: TIDA-00732_Connector (R21.1), TIDA-00732_FPGA_2 (U25.29)
BBB_GPIO10: TIDA-00732_Connector (R23.1), TIDA-00732_FPGA_2 (U25.27)
BBB_GPIO11: TIDA-00732_Connector (R25.1), TIDA-00732_FPGA_2 (U25.24)
BBB_GPIO12: TIDA-00732_Connector (R27.1), TIDA-00732_FPGA_2 (U25.139)
BBB_GPIO13: TIDA-00732_Connector (R29.1), TIDA-00732_FPGA_2 (U25.135)
BBB_GPIO14: TIDA-00732_Connector (R31.1), TIDA-00732_FPGA_2 (U25.117)
BBB_GPIO15: TIDA-00732_Connector (R33.1), TIDA-00732_FPGA_2 (U25.115)
BBB_GPIO16: TIDA-00732_Connector (R35.1), TIDA-00732_FPGA_2 (U25.142)
BBB_GPIO17: TIDA-00732_Connector (R4.2), TIDA-00732_FPGA_2 (U25.70)
BBB_GPIO18: TIDA-00732_Connector (R6.2), TIDA-00732_FPGA_2 (U25.68)
BBB_GPIO19: TIDA-00732_Connector (R8.2), TIDA-00732_FPGA_2 (U25.63)
BBB_GPIO20: TIDA-00732_Connector (R12.2), TIDA-00732_FPGA_2 (U25.55)
BBB_GPIO21: TIDA-00732_Connector (R14.2), TIDA-00732_FPGA_2 (U25.51)
BBB_GPIO22: TIDA-00732_Connector (R16.2), TIDA-00732_FPGA_2 (U25.49)
BBB_GPIO23: TIDA-00732_Connector (R18.2), TIDA-00732_FPGA_2 (U25.47)
BBB_GPIO24: TIDA-00732_Connector (R20.2), TIDA-00732_FPGA_2 (U25.32)
BBB_GPIO25: TIDA-00732_Connector (R22.2), TIDA-00732_FPGA_2 (U25.30)
BBB_GPIO26: TIDA-00732_Connector (R24.2), TIDA-00732_FPGA_2 (U25.28)
BBB_GPIO27: TIDA-00732_Connector (R26.2), TIDA-00732_FPGA_2 (U25.25)
BBB_GPIO28: TIDA-00732_Connector (R28.2), TIDA-00732_FPGA_2 (U25.21)
BBB_GPIO29: TIDA-00732_Connector (R30.2), TIDA-00732_FPGA_2 (U25.138)
BBB_GPIO30: TIDA-00732_Connector (R32.2), TIDA-00732_FPGA_2 (U25.120)
BBB_GPIO31: TIDA-00732_Connector (R34.2), TIDA-00732_FPGA_2 (U25.116)
BBB_GPIO32: TIDA-00732_Connector (R2.2), TIDA-00732_FPGA_2 (U25.72)
BBB_GPIO35: TIDA-00732_Connector (R127.1), TIDA-00732_FPGA_2 (U25.79)
BBB_GPIO36: TIDA-00732_Connector (R129.1), TIDA-00732_FPGA_2 (U25.83)
BBB_GPIO37: TIDA-00732_Connector (R131.1), TIDA-00732_FPGA_2 (U25.85)
BBB_GPIO38: TIDA-00732_Connector (R133.1), TIDA-00732_FPGA_2 (U25.88)
BBB_GPIO39: TIDA-00732_Connector (R135.1), TIDA-00732_FPGA_2 (U25.98)
BBB_GPIO40: TIDA-00732_Connector (R137.1), TIDA-00732_FPGA_2 (U25.101)
BBB_GPIO42: TIDA-00732_Connector (R141.1), TIDA-00732_FPGA_2 (U25.110)
BBB_GPIO43: TIDA-00732_Connector (R143.1), TIDA-00732_FPGA_2 (U25.112)
BBB_GPIO44: TIDA-00732_Connector (R151.1), TIDA-00732_FPGA_2 (U25.113)
BBB_GPIO47: TIDA-00732_Connector (R128.2), TIDA-00732_FPGA_2 (U25.82)
BBB_GPIO48: TIDA-00732_Connector (R130.2), TIDA-00732_FPGA_2 (U25.84)
BBB_GPIO49: TIDA-00732_Connector (R132.2), TIDA-00732_FPGA_2 (U25.87)
BBB_GPIO50: TIDA-00732_Connector (R134.2), TIDA-00732_FPGA_2 (U25.96)
BBB_GPIO52: TIDA-00732_Connector (R142.2), TIDA-00732_FPGA_2 (U25.111)
BBB_GPIO53: TIDA-00732_Connector (R152.2), TIDA-00732_FPGA_2 (U25.114)
BBB_GPIO54: TIDA-00732_Connector (R136.2), TIDA-00732_FPGA_2 (U25.99)
BBB_GPO0: TIDA-00732_Connector (R9.1), TIDA-00732_FPGA_2 (U25.57)
BBB_GPO1: TIDA-00732_Connector (R10.2), TIDA-00732_FPGA_2 (U25.59)
BBB_SYS_RESETN: TIDA-00732_Connector (J2.10), TIDA-00732_FPGA_2 (U25.90)
BCLK_ISO: TIDA-00732_ADC (U33.2), TIDA-00732_FPGA_1 (R167.2 TP48.1 U24.124)
CONVST: TIDA-00732_Isolator (U5.5), TIDA-00732_FPGA_2 (U25.91)
CSn: TIDA-00732_Isolator (U9.4), TIDA-00732_FPGA_2 (U25.3)
EVM1_ADC_CONVST: TIDA-00732_Connector (R163.1), TIDA-00732_FPGA_1 (U24.93)
EVM1_ADC_CSn: TIDA-00732_Connector (R164.1), TIDA-00732_FPGA_1 (U24.92)
EVM1_ADC_RESETn: TIDA-00732_Connector (R160.1), TIDA-00732_FPGA_1 (U24.104)
EVM1_ADC_RVS: TIDA-00732_Connector (R170.1), TIDA-00732_FPGA_1 (U24.90)
EVM1_ADC_SCLK: TIDA-00732_Connector (R166.1 R169.1), TIDA-00732_FPGA_1 (U24.91)
EVM1_ADC_SDI: TIDA-00732_Connector (R162.1), TIDA-00732_FPGA_1 (U24.101)
EVM1_ADC_SDO0: TIDA-00732_Connector (R171.1), TIDA-00732_FPGA_1 (U24.84)
EVM1_ADC_SDO1: TIDA-00732_Connector (R172.1), TIDA-00732_FPGA_1 (U24.77)
EVM1_ADC_SDO2: TIDA-00732_Connector (R173.1), TIDA-00732_FPGA_1 (U24.76)
EVM1_ADC_SDO3: TIDA-00732_Connector (R175.1), TIDA-00732_FPGA_1 (U24.75)
EVM2_ADC_CONVST: TIDA-00732_Connector (R190.1), TIDA-00732_FPGA_2 (U25.121)
EVM2_ADC_CSn: TIDA-00732_Connector (R193.1), TIDA-00732_FPGA_2 (U25.126)
EVM2_ADC_RESETn: TIDA-00732_Connector (R186.1), TIDA-00732_FPGA_2 (U25.125)
EVM2_ADC_RVS: TIDA-00732_Connector (R200.1), TIDA-00732_FPGA_2 (U25.129)
EVM2_ADC_SCLK: TIDA-00732_Connector (R195.1 R199.1), TIDA-00732_FPGA_2 (U25.127)
EVM2_ADC_SDI: TIDA-00732_Connector (R189.1), TIDA-00732_FPGA_2 (U25.124)
EVM2_ADC_SDO0: TIDA-00732_Connector (R210.1), TIDA-00732_FPGA_2 (U25.130)
EVM2_ADC_SDO1: TIDA-00732_Connector (R212.1), TIDA-00732_FPGA_2 (U25.131)
EVM2_ADC_SDO2: TIDA-00732_Connector (R213.1), TIDA-00732_FPGA_2 (U25.132)
EVM2_ADC_SDO3: TIDA-00732_Connector (R215.1), TIDA-00732_FPGA_2 (U25.134)
FSTS0_LED: TIDA-00732_Connector (R123.1), TIDA-00732_FPGA_2 (R209.1 U25.75)
FSTS1_LED: TIDA-00732_Connector (R124.2), TIDA-00732_FPGA_2 (R264.1 U25.76)
FSTS2_LED: TIDA-00732_Connector (R125.1), TIDA-00732_FPGA_2 (R266.1 U25.77)
FSTS3_LED: TIDA-00732_Connector (R126.2), TIDA-00732_FPGA_2 (R265.1 U25.78)
ISO_ADC_CONVST: TIDA-00732_Isolator (U5.12), TIDA-00732_FPGA_1 (U24.71)
ISO_ADC_CSn: TIDA-00732_Isolator (U9.13), TIDA-00732_FPGA_1 (U24.51)
ISO_ADC_RESETn: TIDA-00732_Isolator (U5.14), TIDA-00732_FPGA_1 (U24.69)
ISO_ADC_RVS: TIDA-00732_Isolator (U9.11), TIDA-00732_FPGA_1 (U24.58)
ISO_ADC_SCLK: TIDA-00732_Isolator (U5.13), TIDA-00732_FPGA_1 (U24.70)
ISO_ADC_SDI: TIDA-00732_Isolator (U9.14), TIDA-00732_FPGA_1 (U24.50)
ISO_ADC_SDO0: TIDA-00732_Isolator (U12.6), TIDA-00732_FPGA_1 (U24.46)
ISO_ADC_SDO1: TIDA-00732_Isolator (U12.3), TIDA-00732_FPGA_1 (U24.49)
ISO_ADC_SDO2: TIDA-00732_Isolator (U12.4), TIDA-00732_FPGA_1 (U24.48)
ISO_ADC_SDO3: TIDA-00732_Isolator (U12.5), TIDA-00732_FPGA_1 (U24.47)
ISO_SCL: TIDA-00732_Isolator (R206.1 U35.6), TIDA-00732_ADC_Ref_Select (R271.1 U36.8)
ISO_SDA: TIDA-00732_Isolator (R204.1 U35.7), TIDA-00732_ADC_Ref_Select (R270.1 U36.7)
MCLK: TIDA-00732_FPGA_1 (U24.125), TIDA-00732_ADC_Ref_Select (R273.2)
NISO_SCL: TIDA-00732_Isolator (R50.1 U35.3), TIDA-00732_FPGA_2 (U25.103)
NISO_SDA: TIDA-00732_Isolator (R205.1 U35.2), TIDA-00732_FPGA_2 (U25.104)
OPA625_CM: TIDA-00732_ADC (C65.1 C70.1 U18.3 U20.3), TIDA-00732_ADC_Ref_Select (R106.2 R110.2)
REFBUF: TIDA-00732_ADC (U19.5 U19.7), TIDA-00732_ADC_Ref_Select (R48.1 R49.1 R268.2 R276.2)
REFOUT: TIDA-00732_ADC (R100.1 R108.2), TIDA-00732_ADC_Ref_Select (5 pins)
RVS: TIDA-00732_Isolator (U9.6), TIDA-00732_FPGA_2 (U25.93)
SCLK: TIDA-00732_Isolator (U5.4), TIDA-00732_FPGA_2 (U25.92)
SDI: TIDA-00732_Isolator (U9.3), TIDA-00732_FPGA_2 (U25.4)
SDO0: TIDA-00732_Isolator (U12.11), TIDA-00732_FPGA_2 (U25.8)
SDO1: TIDA-00732_Isolator (U12.14), TIDA-00732_FPGA_2 (U25.5)
SDO2: TIDA-00732_Isolator (U12.13), TIDA-00732_FPGA_2 (U25.6)
SDO3: TIDA-00732_Isolator (U12.12), TIDA-00732_FPGA_2 (U25.7)
SRESETn: TIDA-00732_Isolator (U5.3), TIDA-00732_FPGA_2 (U25.105)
